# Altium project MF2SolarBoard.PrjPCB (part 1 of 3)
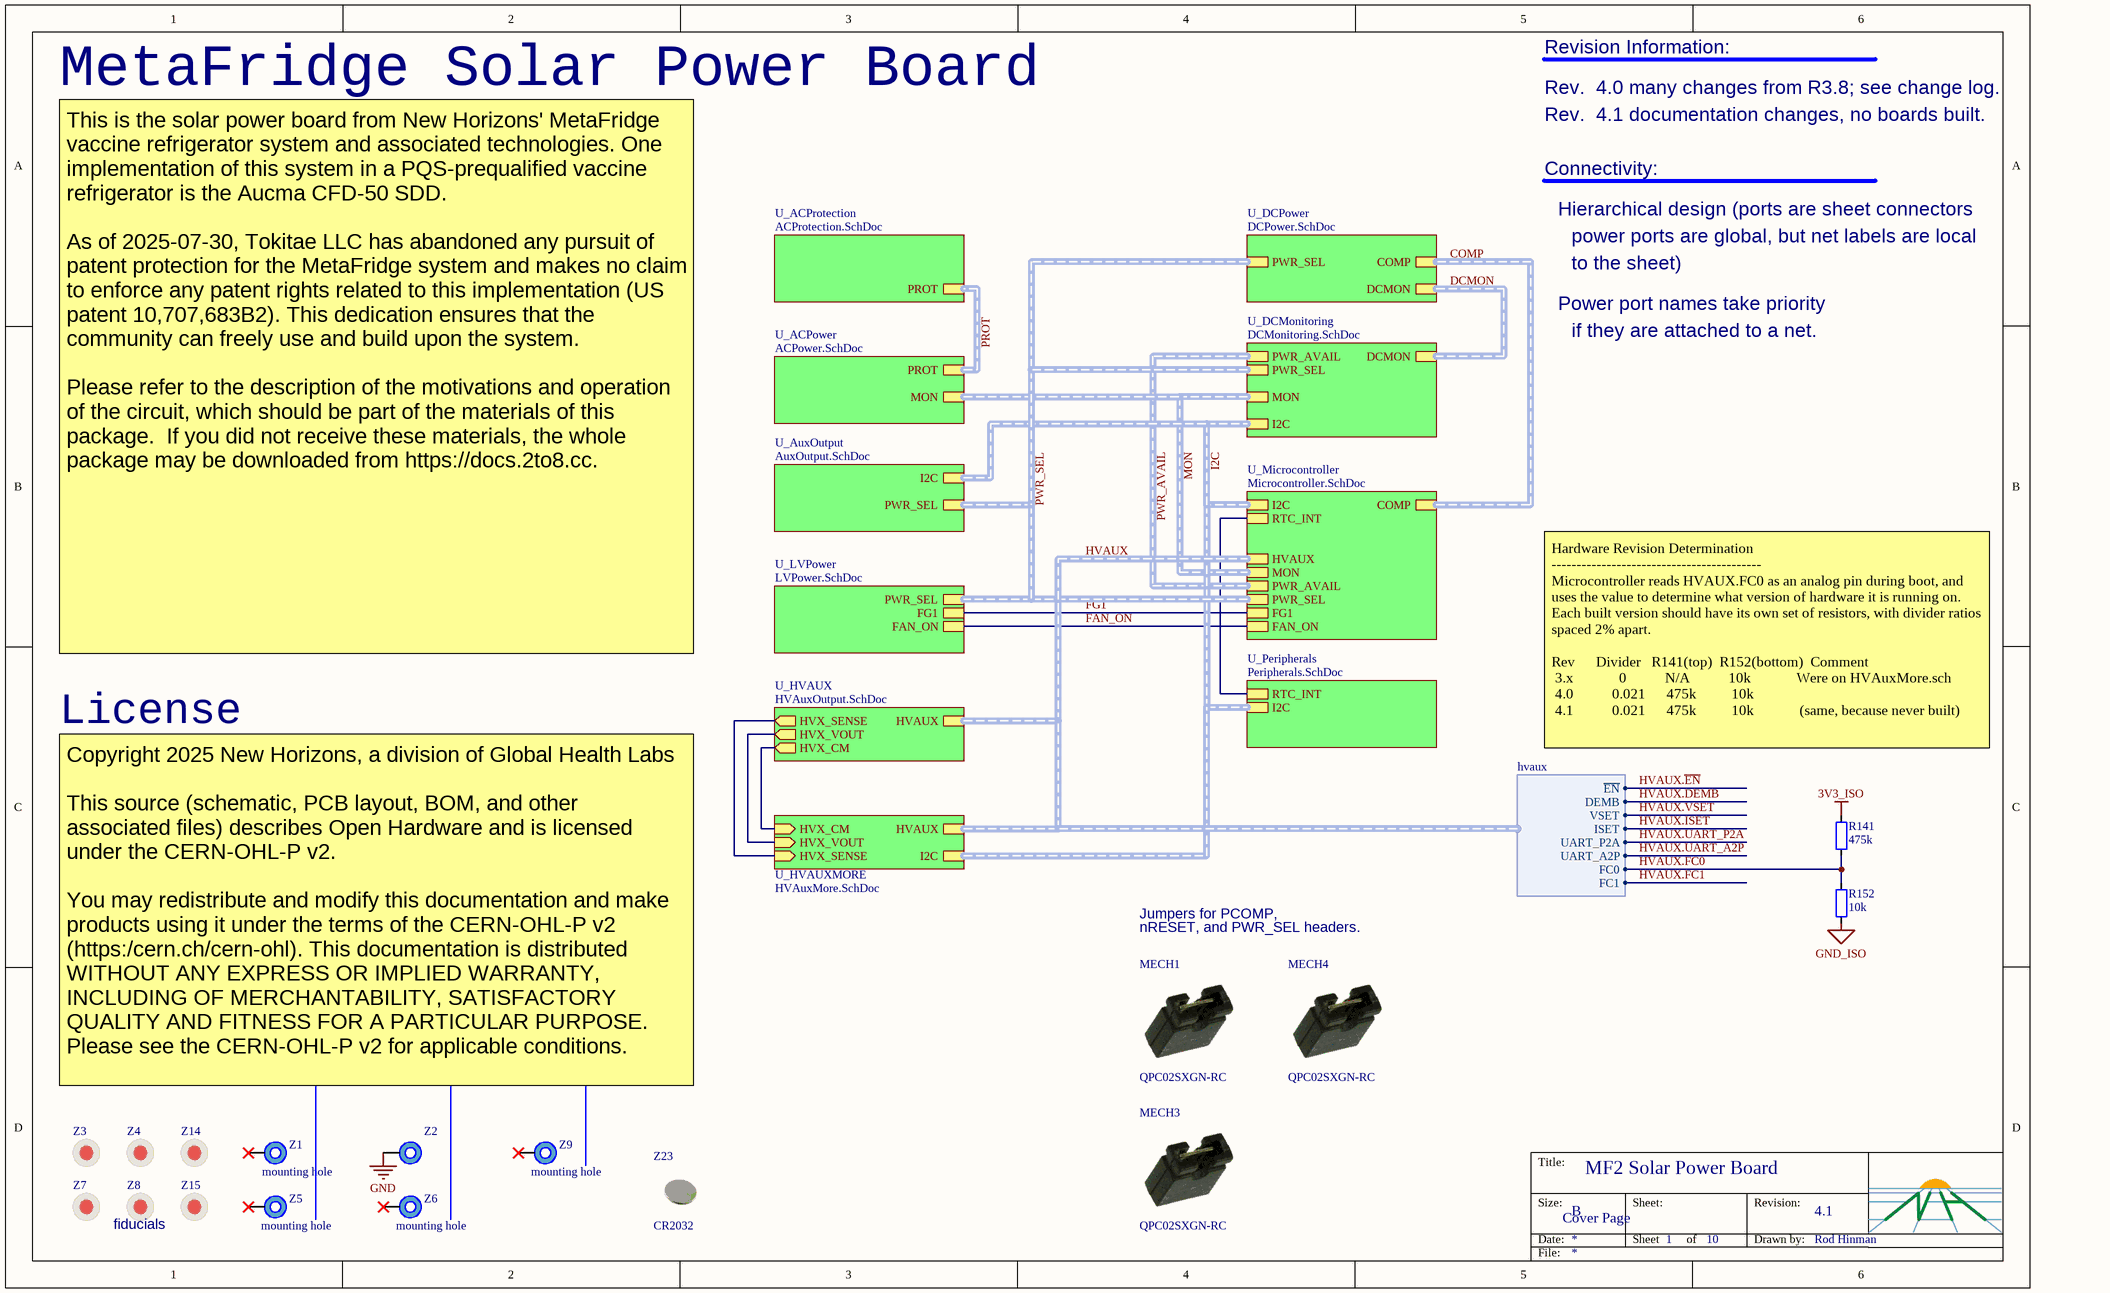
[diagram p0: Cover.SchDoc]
nhToday: 2020-03-06; nhSheetTotal: 10; nhRev: 4.1; nhProjName: MF2 Solar Power Board; nhEngPhone: 808-989-0977; nhEngName: Rod Hinman; nhEngEmail: rod@auroraresearch.com
11 sheets, 685 parts. Net scope: hierarchical (ports join the sheet entries above them; power ports are global).
Board file: PwrBrdPCB.PcbDoc
Sheets:
  Cover.SchDoc
    U_DCMonitoring = DCMonitoring.SchDoc
    U_Microcontroller = Microcontroller.SchDoc
    U_LVPower = LVPower.SchDoc
    U_DCPower = DCPower.SchDoc
    U_ACProtection = ACProtection.SchDoc
    U_ACPower = ACPower.SchDoc
    U_AuxOutput = AuxOutput.SchDoc
    U_Peripherals = Peripherals.SchDoc
    U_HVAUX = HVAuxOutput.SchDoc
    U_HVAUXMORE = HVAuxMore.SchDoc

## Sheet Cover.SchDoc
size B; SheetNumber: 1; nhSheetName: Cover Page

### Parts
MECH1  manufacturer_pn: QPC02SXGN-RC  [SULLINS_QPC02SXGN-RC]  (hidden comment: jumper)
MECH3  manufacturer_pn: QPC02SXGN-RC  [SULLINS_QPC02SXGN-RC]  (hidden comment: jumper)
MECH4  manufacturer_pn: QPC02SXGN-RC  [SULLINS_QPC02SXGN-RC]  (hidden comment: jumper)
R141  value_text: 475k  [RESC1608X05AN[0603]]  (hidden comment: 1/10W 0603 1%)
R152  value_text: 10k  [RESC1608X05AN[0603]]  (hidden comment: 1/10W 0603 1%)
Z1  mounting hole  [MOUNT_HOLE_5MM_8MM]  (no BOM)
Z2  mounting hole  [MOUNT_HOLE_5MM_8MM]  (value not drawn)  (no BOM)
Z3  NOBOM-00010  [FIDUCIAL_1_3_KEEPOUT]  (value not drawn)  (no BOM)
Z4  NOBOM-00010  [FIDUCIAL_1_3_KEEPOUT]  (value not drawn)  (no BOM)
Z5  mounting hole  [MOUNT_HOLE_5MM_8MM]  (no BOM)
Z6  mounting hole  [MOUNT_HOLE_5MM_8MM]  (no BOM)
Z7  NOBOM-00010  [FIDUCIAL_1_3_KEEPOUT]  (value not drawn)  (no BOM)
Z8  NOBOM-00010  [FIDUCIAL_1_3_KEEPOUT]  (value not drawn)  (no BOM)
Z9  mounting hole  [MOUNT_HOLE_5MM_8MM]  (no BOM)
Z14  NOBOM-00010  [FIDUCIAL_1_3_KEEPOUT]  (value not drawn)  (no BOM)
Z15  NOBOM-00010  [FIDUCIAL_1_3_KEEPOUT]  (value not drawn)  (no BOM)
Z23  CR2032  [COIN_CELL_2032]  (mechanical)

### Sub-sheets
U_ACPower = ACPower.SchDoc: PROT (harness prot), MON (harness mon-data)
U_ACProtection = ACProtection.SchDoc: PROT (harness prot)
U_AuxOutput = AuxOutput.SchDoc: I2C (harness i2c), PWR_SEL (harness pwr_sel)
U_DCMonitoring = DCMonitoring.SchDoc: MON (harness mon-data), PWR_AVAIL (harness avail), DCMON (harness dc-mon), I2C (harness i2c), PWR_SEL (harness pwr_sel)
U_DCPower = DCPower.SchDoc: COMP (harness comp), DCMON (harness dc-mon), PWR_SEL (harness pwr_sel)
U_HVAUX = HVAuxOutput.SchDoc: HVAUX (harness hvaux), HVX_CM (out), HVX_VOUT (out), HVX_SENSE (out)
U_HVAUXMORE = HVAuxMore.SchDoc: I2C (harness i2c), HVAUX (harness hvaux), HVX_CM (in), HVX_VOUT (in), HVX_SENSE (in)
U_LVPower = LVPower.SchDoc: FG1, FAN_ON, PWR_SEL (harness pwr_sel)
U_Microcontroller = Microcontroller.SchDoc: MON (harness mon-data), PWR_AVAIL (harness avail), FG1, FAN_ON, COMP (harness comp), I2C (harness i2c), RTC_INT, PWR_SEL (harness pwr_sel), HVAUX (harness hvaux)
U_Peripherals = Peripherals.SchDoc: RTC_INT, I2C (harness i2c)

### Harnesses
hvaux: ~{EN}, VSET, UART_P2A, UART_A2P, FC0, FC1, ISET, DEMB

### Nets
3V3_ISO: R141.1
GND: Z2.0
GND_ISO: R152.1
FAN_ON: sheet U_Microcontroller/FAN_ON, sheet U_LVPower/FAN_ON
FG1: sheet U_Microcontroller/FG1, sheet U_LVPower/FG1
HVAUX.FC0: R141.2 R152.2 ; sheet U_Microcontroller/HVAUX.FC0
HVX_CM: sheet U_HVAUX/HVX_CM, sheet U_HVAUXMORE/HVX_CM
HVX_VOUT: sheet U_HVAUX/HVX_VOUT, sheet U_HVAUXMORE/HVX_VOUT
RTC_INT: sheet U_Microcontroller/RTC_INT, sheet U_Peripherals/RTC_INT
NetL8_1: sheet U_HVAUX/HVX_SENSE, sheet U_HVAUXMORE/HVX_SENSE

Not connected (* = marked no-connect by the designer): Z1 0*; Z5 0*; Z6 0*; Z9 0*

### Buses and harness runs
harness COMP = sheet U_DCPower/COMP = sheet U_Microcontroller/COMP
harness DCMON = sheet U_DCMonitoring/DCMON = sheet U_DCPower/DCMON
harness HVAUX = sheet U_HVAUX/HVAUX = sheet U_HVAUXMORE/HVAUX = sheet U_Microcontroller/HVAUX
harness I2C = sheet U_AuxOutput/I2C = sheet U_DCMonitoring/I2C = sheet U_HVAUXMORE/I2C = sheet U_Microcontroller/I2C = sheet U_Peripherals/I2C
harness MON = sheet U_ACPower/MON = sheet U_DCMonitoring/MON = sheet U_Microcontroller/MON
harness PROT = sheet U_ACPower/PROT = sheet U_ACProtection/PROT
harness PWR_AVAIL = sheet U_DCMonitoring/PWR_AVAIL = sheet U_Microcontroller/PWR_AVAIL
harness PWR_SEL = sheet U_AuxOutput/PWR_SEL = sheet U_DCMonitoring/PWR_SEL = sheet U_DCPower/PWR_SEL = sheet U_LVPower/PWR_SEL = sheet U_Microcontroller/PWR_SEL

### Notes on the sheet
- MetaFridge Solar Power Board
- Rev.  4.0 many changes from R3.8; see change log.
- Revision Information:
- Rev.  4.1 documentation changes, no boards built.
- Connectivity:
- Hierarchical design (ports are sheet connectors
- power ports are global, but net labels are local
- to the sheet)
- Power port names take priority
- if they are attached to a net.
- This is the solar power board from New Horizons' MetaFridge vaccine refrigerator system and associated technologies. One implementation of this system in a PQS-prequalified vaccine refrigerator is the Aucma CFD-50 SDD.
  As of 2025-07-30, Tokitae LLC has abandoned any pursuit of patent protection for the MetaFridge system and makes no claim to enforce any patent rights related to this implementation (US patent 10,707,683B2). This dedication ensures that the community can freely use and build upon the system.
  Please refer to the description of the motivations and operation of the circuit, which should be part of the materials of this package.  If you did not receive these materials, the whole package may be downloaded from https://docs.2to8.cc.
- License
- Hardware Revision Determination
  ------------------------------------------
  Microcontroller reads HVAUX.FC0 as an analog pin during boot, and uses the value to determine what version of hardware it is running on.  Each built version should have its own set of resistors, with divider ratios spaced 2% apart.
  Rev      Divider   R141(top)  R152(bottom)  Comment
  3.x             0           N/A           10k             Were on HVAuxMore.sch
  4.0           0.021      475k          10k
  4.1           0.021      475k          10k             (same, because never built)
- Jumpers for PCOMP,
- nRESET, and PWR_SEL headers.
- Miscellaneous Mechanicals
- Copyright 2025 New Horizons, a division of Global Health Labs
  This source (schematic, PCB layout, BOM, and other associated files) describes Open Hardware and is licensed under the CERN-OHL-P v2.
  You may redistribute and modify this documentation and make products using it under the terms of the CERN-OHL-P v2 (https:/cern.ch/cern-ohl). This documentation is distributed WITHOUT ANY EXPRESS OR IMPLIED WARRANTY, INCLUDING OF MERCHANTABILITY, SATISFACTORY QUALITY AND FITNESS FOR A PARTICULAR PURPOSE. Please see the CERN-OHL-P v2 for applicable conditions.
- fiducials

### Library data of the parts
MECH1 MECH3 MECH4 = MECH-00014: 2 (1 x 2) Position Shunt Connector Black Open Top 0.100" (2.54mm) Gold; manufacturer: Sullins Connector Solutions; id: 138116
R141 = RES-00032: RES SMD 475K OHM 1% 1/10W 0603; manufacturer: Panasonic Electronic Components; manufacturer_pn: ERJ-3EKF4753V; id: 137110; value: 475000; Key Parameters: 1% required
R152 = RES-00107: 10 kOhms ±1% 0.1W, 1/10W Chip Resistor 0603 (1608 Metric) Automotive AEC-Q200 Thick Film; manufacturer_pn: ERJ-3EKF1002V; manufacturer: Panasonic Electronic Components; id: 182861; value: 10000; Key Parameters: 1% required
Z1 Z2 Z5 Z6 Z9 = NOBOM-00011: Mounting hole, 5mm hole, 8mm pad; manufacturer: New Horizons; id: 138119
Z3 Z4 Z7 Z8 Z14 Z15 = NOBOM-00010: Fiducial, 1mm dia, 3mm solder mask opening; manufacturer: New Horizons; id: 138118
Z23 = MECH-00025: Lithium Battery Non-Rechargeable (Primary) 3V Coin, 20.0mm; manufacturer: Panasonic Electronic Components; id: 141799

## Sheet DCMonitoring.SchDoc
size B; SheetNumber: 3; nhSheetName: DC Monitoring
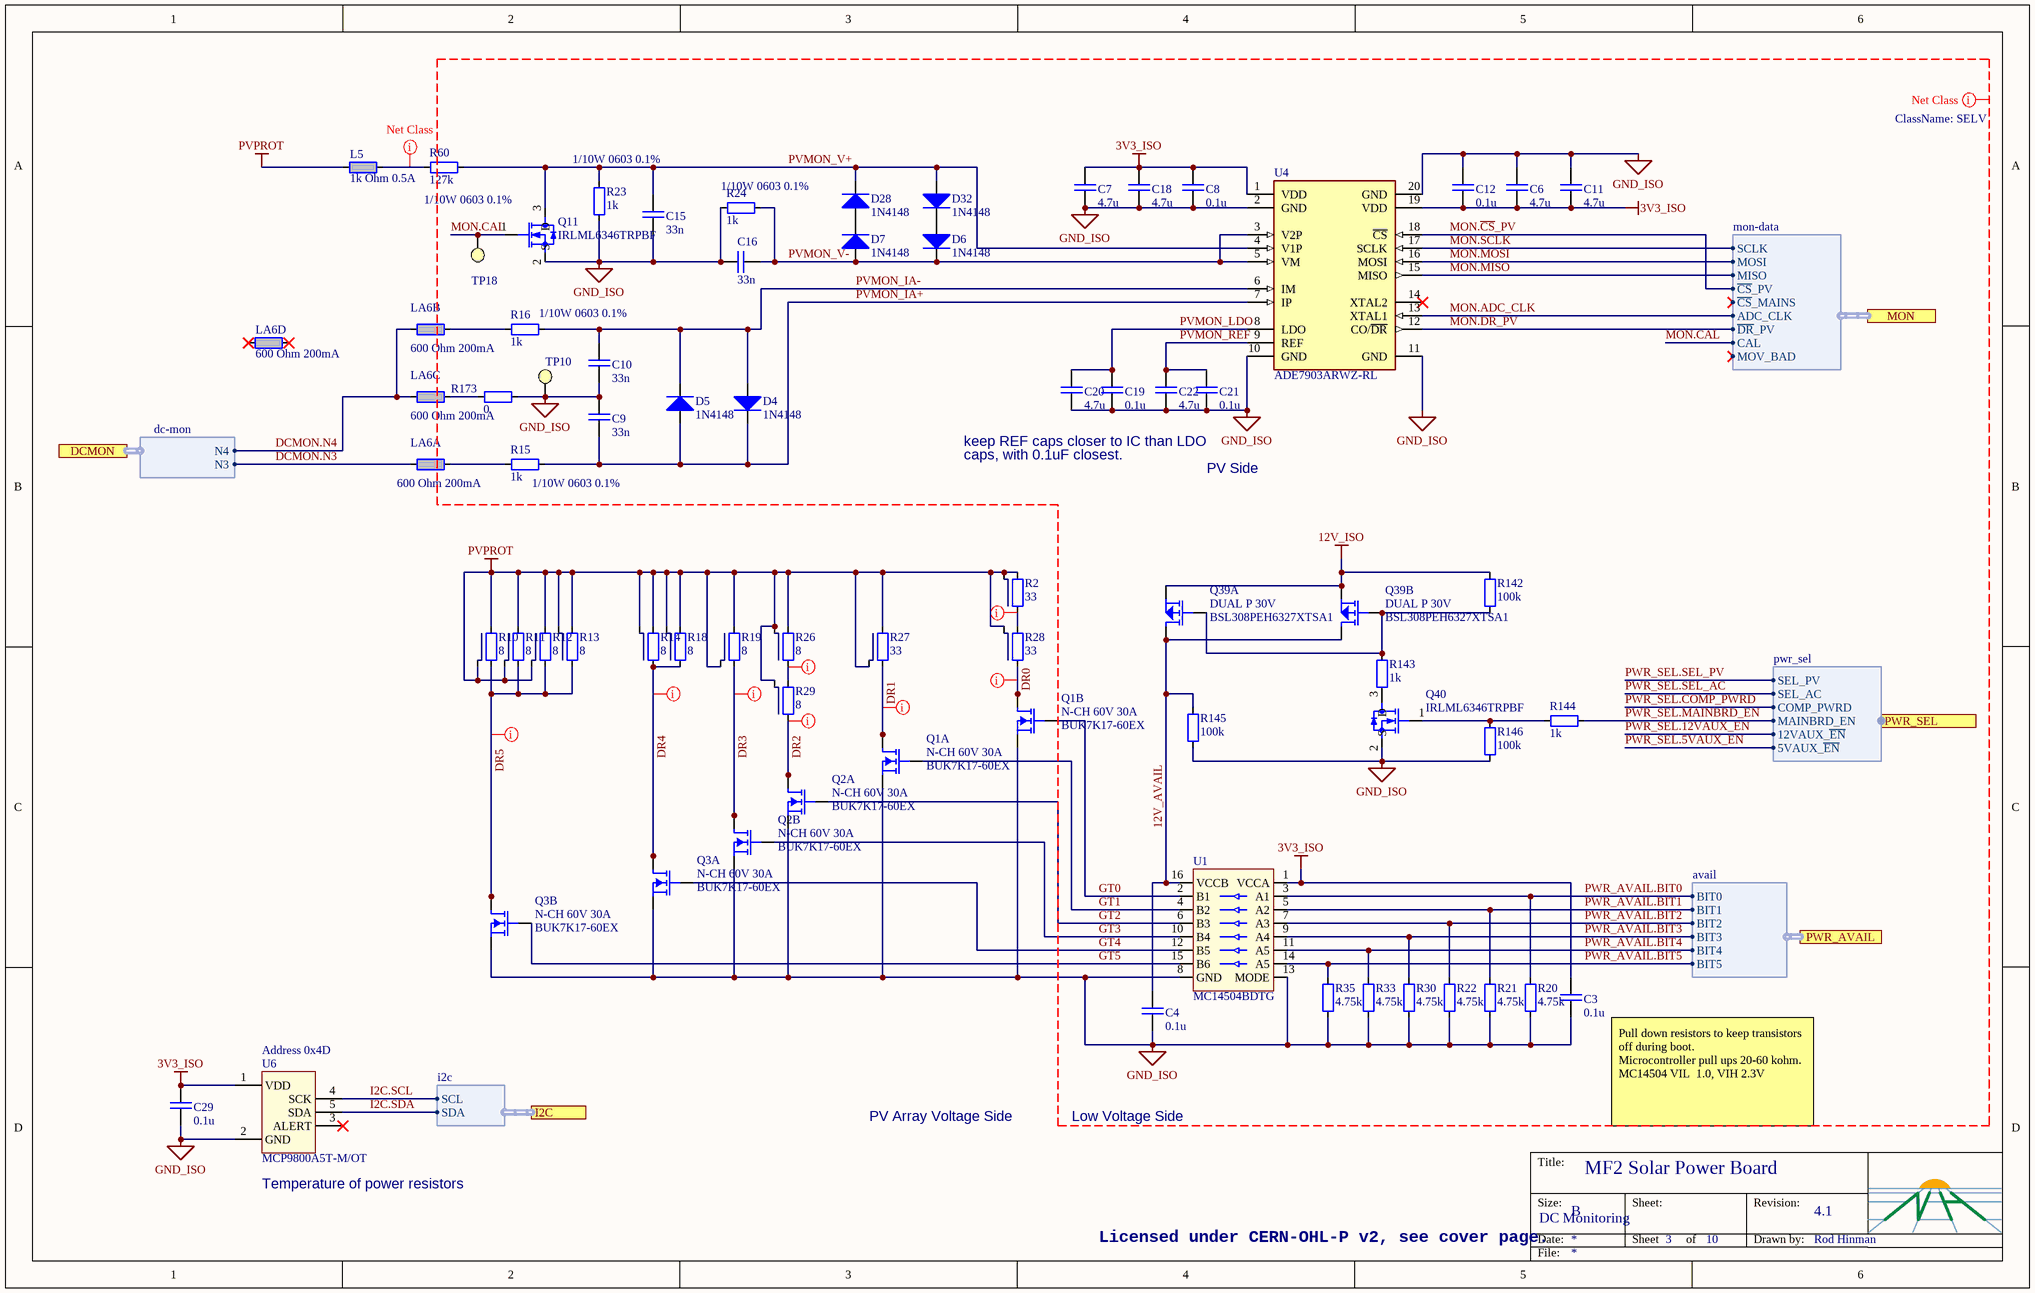
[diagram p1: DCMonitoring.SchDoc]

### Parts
C3  value_text: 0.1u  [CAPC1608X09N[0603]]  (hidden comment: 50V X7R 0603)
C4  value_text: 0.1u  [CAPC1608X09N[0603]]  (hidden comment: 50V X7R 0603)
C6  value_text: 4.7u  [CAPC1608X09N[0603]]  (hidden comment: 25V X6S 0603)
C7  value_text: 4.7u  [CAPC1608X09N[0603]]  (hidden comment: 25V X6S 0603)
C8  value_text: 0.1u  [CAPC1608X09N[0603]]  (hidden comment: 50V X7R 0603)
C9  value_text: 33n  [CAPC1608X09N[0603]]  (hidden comment: 50V X7R 0603)
C10  value_text: 33n  [CAPC1608X09N[0603]]  (hidden comment: 50V X7R 0603)
C11  value_text: 4.7u  [CAPC1608X09N[0603]]  (hidden comment: 25V X6S 0603)
C12  value_text: 0.1u  [CAPC1608X09N[0603]]  (hidden comment: 50V X7R 0603)
C15  value_text: 33n  [CAPC1608X09N[0603]]  (hidden comment: 50V X7R 0603)
C16  value_text: 33n  [CAPC1608X09N[0603]]  (hidden comment: 50V X7R 0603)
C18  value_text: 4.7u  [CAPC1608X09N[0603]]  (hidden comment: 25V X6S 0603)
C19  value_text: 0.1u  [CAPC1608X09N[0603]]  (hidden comment: 50V X7R 0603)
C20  value_text: 4.7u  [CAPC1608X09N[0603]]  (hidden comment: 25V X6S 0603)
C21  value_text: 0.1u  [CAPC1608X09N[0603]]  (hidden comment: 50V X7R 0603)
C22  value_text: 4.7u  [CAPC1608X09N[0603]]  (hidden comment: 25V X6S 0603)
C29  value_text: 0.1u  [CAPC1608X09N[0603]]  (hidden comment: 50V X7R 0603)
D4  1N4148  [SOD-123]
D5  1N4148  [SOD-123]
D6  1N4148  [SOD-123]
D7  1N4148  [SOD-123]
D28  1N4148  [SOD-123]
D32  1N4148  [SOD-123]
L5  1k Ohm 0.5A  [INDC2012X110N[0805]]
LA6  600 Ohm 200mA  [FERCAV80P320X160X70-4]  (parts A,B,C,D of 4)
Q1  N-CH 60V 30A  manufacturer_pn: BUK7K17-60EX  [SOT1205_LFPAK56D]  (parts A,B of 2)
Q2  N-CH 60V 30A  manufacturer_pn: BUK7K17-60EX  [SOT1205_LFPAK56D]  (parts A,B of 2)
Q3  N-CH 60V 30A  manufacturer_pn: BUK7K17-60EX  [SOT1205_LFPAK56D]  (parts A,B of 2)
Q11  manufacturer_pn: IRLML6346TRPBF  [SOT23-3]  (hidden comment: N-CH 30V 3.4A)
Q39  DUAL P 30V  manufacturer_pn: BSL308PEH6327XTSA1  [SOT_23_6]  (parts A,B of 2)
Q40  manufacturer_pn: IRLML6346TRPBF  [SOT23-3]  (hidden comment: N-CH 30V 3.4A)
R2  value_text: 33  [BOURNS_PWR163]  (hidden comment: 25W DPAK 1%)
R10  value_text: 8  [TO263_PWR_RES]  (hidden comment: 35W D2PAK 1%)
R11  value_text: 8  [TO263_PWR_RES]  (hidden comment: 35W D2PAK 1%)
R12  value_text: 8  [TO263_PWR_RES]  (hidden comment: 35W D2PAK 1%)
R13  value_text: 8  [TO263_PWR_RES]  (hidden comment: 35W D2PAK 1%)
R14  value_text: 8  [TO263_PWR_RES]  (hidden comment: 35W D2PAK 1%)
R15  1/10W 0603 0.1%  value_text: 1k  [RESC1608X05AN[0603]]
R16  1/10W 0603 0.1%  value_text: 1k  [RESC1608X05AN[0603]]
R18  value_text: 8  [TO263_PWR_RES]  (hidden comment: 35W D2PAK 1%)
R19  value_text: 8  [TO263_PWR_RES]  (hidden comment: 35W D2PAK 1%)
R20  value_text: 4.75k  [RESC1608X05AN[0603]]  (hidden comment: 1/10W 0603 1%)
R21  value_text: 4.75k  [RESC1608X05AN[0603]]  (hidden comment: 1/10W 0603 1%)
R22  value_text: 4.75k  [RESC1608X05AN[0603]]  (hidden comment: 1/10W 0603 1%)
R23  1/10W 0603 0.1%  value_text: 1k  [RESC1608X05AN[0603]]
R24  1/10W 0603 0.1%  value_text: 1k  [RESC1608X05AN[0603]]
R26  value_text: 8  [TO263_PWR_RES]  (hidden comment: 35W D2PAK 1%)
R27  value_text: 33  [BOURNS_PWR163]  (hidden comment: 25W DPAK 1%)
R28  value_text: 33  [BOURNS_PWR163]  (hidden comment: 25W DPAK 1%)
R29  value_text: 8  [TO263_PWR_RES]  (hidden comment: 35W D2PAK 1%)
R30  value_text: 4.75k  [RESC1608X05AN[0603]]  (hidden comment: 1/10W 0603 1%)
R33  value_text: 4.75k  [RESC1608X05AN[0603]]  (hidden comment: 1/10W 0603 1%)
R35  value_text: 4.75k  [RESC1608X05AN[0603]]  (hidden comment: 1/10W 0603 1%)
R60  1/10W 0603 0.1%  value_text: 127k  [RESC1608X05AN[0603]]
R142  value_text: 100k  [RESC1608X05AN[0603]]  (hidden comment: 1/10W 0603 1%)
R143  value_text: 1k  [RESC1608X05AN[0603]]  (hidden comment: 1/10W 0603 1%)
R144  value_text: 1k  [RESC1608X05AN[0603]]  (hidden comment: 1/10W 0603 1%)
R145  value_text: 100k  [RESC1608X05AN[0603]]  (hidden comment: 1/10W 0603 1%)
R146  value_text: 100k  [RESC1608X05AN[0603]]  (hidden comment: 1/10W 0603 1%)
R173  value_text: 0  [RESC1608X05AN[0603]]  (hidden comment: 1/10W 0603 Jumper)
TP10  TP SMD 1.5mm  [TP_SMD_Ø1.5mm]  (value not drawn)  (no BOM)
TP18  TP SMD 1.5mm  [TP_SMD_Ø1.5mm]  (value not drawn)  (no BOM)
U1  manufacturer_pn: MC14504BDTG  [TSSOP16_ON]  (hidden comment: Logic level translator)
U4  manufacturer_pn: ADE7903ARWZ-RL  [SOIC127P1030X265-20N_smaller]  (hidden comment: ADE7903)
U6  Address 0x4D  manufacturer_pn: MCP9800A5T-M/OT  [SOT-23-5]

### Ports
DCMON (harness dc-mon), I2C (harness i2c), MON (harness mon-data), PWR_AVAIL (harness avail), PWR_SEL (harness pwr_sel)

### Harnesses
dc-mon: N4, N3
avail: BIT0, BIT1, BIT2, BIT3, BIT5, BIT4
mon-data: SCLK, MOSI, MISO, ~{CS}_PV, ADC_CLK, ~{DR}_PV, ~{CS}_MAINS, MOV_BAD, CAL
i2c: SDA, SCL
pwr_sel: SEL_PV, SEL_AC, COMP_PWRD, 12VAUX_~{EN}, 5VAUX_~{EN}, MAINBRD_EN

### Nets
3V3_ISO: C3.1 C6.2 C7.1 C8.1 C11.2 C12.2 C18.1 C29.1 U1.1(VCCA) U4.1(VDD) U4.19(VDD) U6.1(VDD)
12V_ISO: Q39.2(S2) Q39.5(S1) R142.2
GND_ISO: C3.2 C4.2 C6.1 C7.2 C8.2 C9.2 C10.1 C11.1 C12.1 C15.2 C16.2 C18.2 C19.2 C20.2 C21.2 C22.2 C29.2 Q1.1(S1) Q1.3(S2) Q2.1(S1) Q2.3(S2) Q3.1(S1) Q3.3(S2) Q11.2(S) Q40.2(S) R20.2 R21.2 R22.1 R23.1 R24.1 R30.2 R33.2 R35.1 R145.1 R146.1 R173.2 TP10.1 U1.8(GND) U1.13(MODE) U4.2(GND) U4.10(GND) U4.11(GND) U4.20(GND) U6.2(GND)
PVPROT: L5.1 R2.2 R2.3 R10.1 R10.3 R11.1 R11.3 R12.1 R12.3 R13.2 R13.3 R14.2 R14.3 R18.2 R18.3 R19.1 R19.3 R26.2 R26.3 R27.1 R27.3 R28.3 R29.3
12V_AVAIL: C4.1 Q39.4(D2) Q39.6(D1) R145.2 U1.16(VCCB)
DCMON.N3: LA6.1 ; port DCMON.N3
DCMON.N4: LA6.2 LA6.3 ; port DCMON.N4
DR0: Q1.5(D2) Q1.6(D2) R28.1
DR1: Q1.7(D1) Q1.8(D1) R27.2
DR2: Q2.7(D1) Q2.8(D1) R29.1
DR3: Q2.5(D2) Q2.6(D2) R19.2
DR4: Q3.7(D1) Q3.8(D1) R14.1 R18.1
DR5: Q3.5(D2) Q3.6(D2) R10.2 R11.2 R12.2 R13.1
GT0: Q1.4(G2) U1.2(B1)
GT1: Q1.2(G1) U1.4(B2)
GT2: Q2.2(G1) U1.6(B3)
GT3: Q2.4(G2) U1.10(B4)
GT4: Q3.2(G1) U1.12(B5)
GT5: Q3.4(G2) U1.15(B6)
I2C.SCL: U6.4(SCK) ; port I2C.SCL
I2C.SDA: U6.5(SDA) ; port I2C.SDA
MON.ADC_CLK: U4.13(XTAL1) ; port MON.ADC_CLK
MON.~{CS}_PV: U4.18(~{CS}) ; port MON.~{CS}_PV
MON.CAL: Q11.1(G) TP18.1 ; port MON.CAL
MON.~{DR}_PV: U4.12(CO/~{DR}) ; port MON.~{DR}_PV
MON.MISO: U4.15(MISO) ; port MON.MISO
MON.MOSI: U4.16(MOSI) ; port MON.MOSI
MON.SCLK: U4.17(SCLK) ; port MON.SCLK
PVMON_IA+: C9.1 D4.K D5.A R15.2 U4.7(IP)
PVMON_IA-: C10.2 D4.A D5.K R16.1 U4.6(IM)
PVMON_LDO: C19.1 C20.1 U4.8(LDO)
PVMON_REF: C21.1 C22.1 U4.9(REF)
PVMON_V+: C15.1 D28.K D32.A Q11.3(D) R23.2 R60.2 U4.4(V1P)
PVMON_V-: C16.1 D6.K D7.A R24.2 U4.3(V2P) U4.5(VM)
PWR_AVAIL.BIT0: R20.1 U1.3(A1) ; port PWR_AVAIL.BIT0
PWR_AVAIL.BIT1: R21.1 U1.5(A2) ; port PWR_AVAIL.BIT1
PWR_AVAIL.BIT2: R22.2 U1.7(A3) ; port PWR_AVAIL.BIT2
PWR_AVAIL.BIT3: R30.1 U1.9(A4) ; port PWR_AVAIL.BIT3
PWR_AVAIL.BIT4: R33.1 U1.11(A5) ; port PWR_AVAIL.BIT4
PWR_AVAIL.BIT5: R35.2 U1.14(A5) ; port PWR_AVAIL.BIT5
PWR_SEL.MAINBRD_EN: R144.1 ; port PWR_SEL.MAINBRD_EN
NetD6_A: D6.A D32.K
NetD7_K: D7.K D28.A
NetL5_2: L5.2 R60.1
NetLA6_6: LA6.6 R173.1
NetLA6_7: LA6.7 R16.2
NetLA6_8: LA6.8 R15.1
NetQ39_1: Q39.1(G1) Q39.3(G2) R142.1 R143.2
NetQ40_1: Q40.1(G) R144.2 R146.2
NetQ40_3: Q40.3(D) R143.1
NetR2_1: R2.1 R28.2
NetR26_1: R26.1 R29.2

Not connected (* = marked no-connect by the designer): LA6 4* 5*; U4 14(XTAL2)*; U6 3(ALERT)*

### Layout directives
net class PVPOS: DR0, DR1, DR2, DR3, DR4, DR5, NetL5_2, NetR2_1, NetR26_1
net class SELV: 3V3_ISO, 12V_AVAIL, 12V_ISO, DR0, DR1, DR2, DR3, DR4, DR5, GND_ISO, GT0, GT1, GT2, GT3, GT4, GT5, MON.ADC_CLK, MON.CAL, MON.MISO, MON.MOSI, MON.SCLK, MON.~{CS}_PV, MON.~{DR}_PV, PVMON_IA+, PVMON_IA-, PVMON_LDO, PVMON_REF, PVMON_V+, PVMON_V-, PVPROT, PWR_AVAIL.BIT0, PWR_AVAIL.BIT1, PWR_AVAIL.BIT2, PWR_AVAIL.BIT3, PWR_AVAIL.BIT4, PWR_AVAIL.BIT5, PWR_SEL.5VAUX_~{EN}, PWR_SEL.12VAUX_~{EN}, PWR_SEL.COMP_PWRD, PWR_SEL.MAINBRD_EN, PWR_SEL.SEL_AC, PWR_SEL.SEL_PV

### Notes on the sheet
- keep REF caps closer to IC than LDO
- caps, with 0.1uF closest.
- PV Side
- PV Array Voltage Side
- Low Voltage Side
- (near C3) Pull down resistors to keep transistors off during boot.
  Microcontroller pull ups 20-60 kohm.
  MC14504 VIL  1.0, VIH 2.3V
- (near U6) Temperature of power resistors
- Licensed under CERN-OHL-P v2, see cover page.

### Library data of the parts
C3 C4 C8 C12 C19 C21 C29 = CAP-00001: 0.10µF 50V Ceramic Capacitor X7R 0603 (1608 Metric) 0.063" L x 0.031" W (1.60mm x 0.80mm); manufacturer: Murata Electronics North America; manufacturer_pn: GRM188R71H104KA93D; id: 136482; value: 1E-7; Key Parameters: V >= 25V
C6 C7 C11 C18 C20 C22 = CAP-00015: 4.7µF 25V Ceramic Capacitor X6S 0603 (1608 Metric) 0.063" L x 0.031" W (1.60mm x 0.80mm); manufacturer: Murata Electronics North America; manufacturer_pn: GRM188C81E475KE11D; id: 136726; value: 4.7E-6; Key Parameters: V >= 16V
C9 C10 C15 C16 = CAP-00000: 0.033µF 50V Ceramic Capacitor X7R 0603 (1608 Metric) 0.063" L x 0.031" W (1.60mm x 0.80mm); manufacturer: Murata Electronics North America; manufacturer_pn: GRM188R71H333KA61D; id: 136460; value: 3.3E-8; Key Parameters: V >= 16V
D4-D7 D28 D32 = DIO-00004: Diode Standard 100V 150mA Surface Mount SOD-123; manufacturer_pn: 1N4148W-TP; manufacturer: Micro Commercial Co; id: 137134
L5 = FER-00005: FERRITE BEAD 1 KOHM 0805 1LN 0.28 ohm; manufacturer: Murata Electronics North America; manufacturer_pn: BLM21AG102SN1D; id: 137114; value: 1000
LA6 = FER-00009: FERRITE BEAD 600 OHM 1206 4LN; manufacturer_pn: BK32164S601-T; manufacturer: Taiyo Yuden; id: 162218; value: 600
Q1-Q3 = FET-00017: Mosfet Array 2 N-Channel (Dual) 60V 30A 53W Surface Mount LFPAK56D; manufacturer: Nexperia USA Inc.; id: 193253
Q11 Q40 = FET-00002: MOSFET N-CH 30V 3.4A SOT23; manufacturer: Infineon Technologies; id: 137229
Q39 = FET-00023: Mosfet Array 2 P-Channel (Dual) 30V 2A 500mW Surface Mount PG-TSOP-6-6; manufacturer: Infineon Technologies; id: 297421
R2 R27 R28 = RES-00083: RES SMD 33 OHM 1% 25W DPAK; manufacturer_pn: PWR163S-25-33R0F; manufacturer: Bourns Inc.; id: 152903; value: 33
R10-R14 R18 R19 R26 R29 = RES-00082: RES SMD 8 OHM 1% 35W D2PAK; manufacturer_pn: PWR263S-35-8R00F; manufacturer: Bourns Inc.; id: 152902; value: 8
R15 R16 R23 R24 = RES-00067: RES SMD 1KOHM 0.1% 1/10W 0603; manufacturer: Panasonic Electronic Components; manufacturer_pn: ERA-3AEB102V; id: 147997; value: 1000; Key Parameters: 0.1% required
R20-R22 R30 R33 = RES-00013: RES SMD 4.75K OHM 1% 1/10W 0603; manufacturer_pn: ERJ-3EKF4751V; manufacturer: Panasonic Electronic Components; id: 137091; value: 4750; Key Parameters: 5% OK
R35 = RES-00013: RES SMD 4.75K OHM 1% 1/10W 0603; manufacturer: Panasonic Electronic Components; manufacturer_pn: ERJ-3EKF4751V; id: 137091; value: 4750; Key Parameters: 5% OK
R60 = RES-00066: RES SMD 127KOHM 0.1% 1/10W 0603; manufacturer: Panasonic Electronic Components; manufacturer_pn: ERA-3AEB1273V; id: 147994; value: 127000; Key Parameters: 0.1% required
R142 R145 R146 = RES-00112: 100 kOhms ±1% 0.1W, 1/10W Chip Resistor 0603 (1608 Metric) Automotive AEC-Q200 Thick Film; manufacturer: Panasonic Electronic Components; manufacturer_pn: ERJ-3EKF1003V; id: 185358; value: 100000; Key Parameters: 1% required
R143 R144 = RES-00113: 1 kOhms ±1% 0.1W, 1/10W Chip Resistor 0603 (1608 Metric) Automotive AEC-Q200 Thick Film; manufacturer: Panasonic Electronic Components; manufacturer_pn: ERJ-3EKF1001V; id: 185365; value: 1000; Key Parameters: 1% required
R173 = RES-00010: RES SMD 0.0OHM JUMPER 1/10W 0603; manufacturer_pn: ERJ-3GEY0R00V; manufacturer: Panasonic Electronic Components; id: 137088; value: 0
TP10 TP18 = NOBOM-00008: Test point, SMD, 1.5mm dia (0.059"); manufacturer: New Horizons; id: 137590
U1 = ICXCV-00015: IC LEVEL SHIFTER HEX 16-TSSOP; manufacturer: ON Semiconductor; id: 171400
U4 = ICANA-00022: Energy Monitor (Power Meter) 24 bit SPI 20-SOIC; manufacturer: Analog Devices Inc.; id: 169235
U6 = ICANA-00026: Temperature Sensor Digital, Local -55°C ~ 125°C 11 b SOT-23-5; manufacturer: Microchip Technology; id: 178864

## Sheet Microcontroller.SchDoc
size B; SheetNumber: 10; nhSheetName: Microcontroller
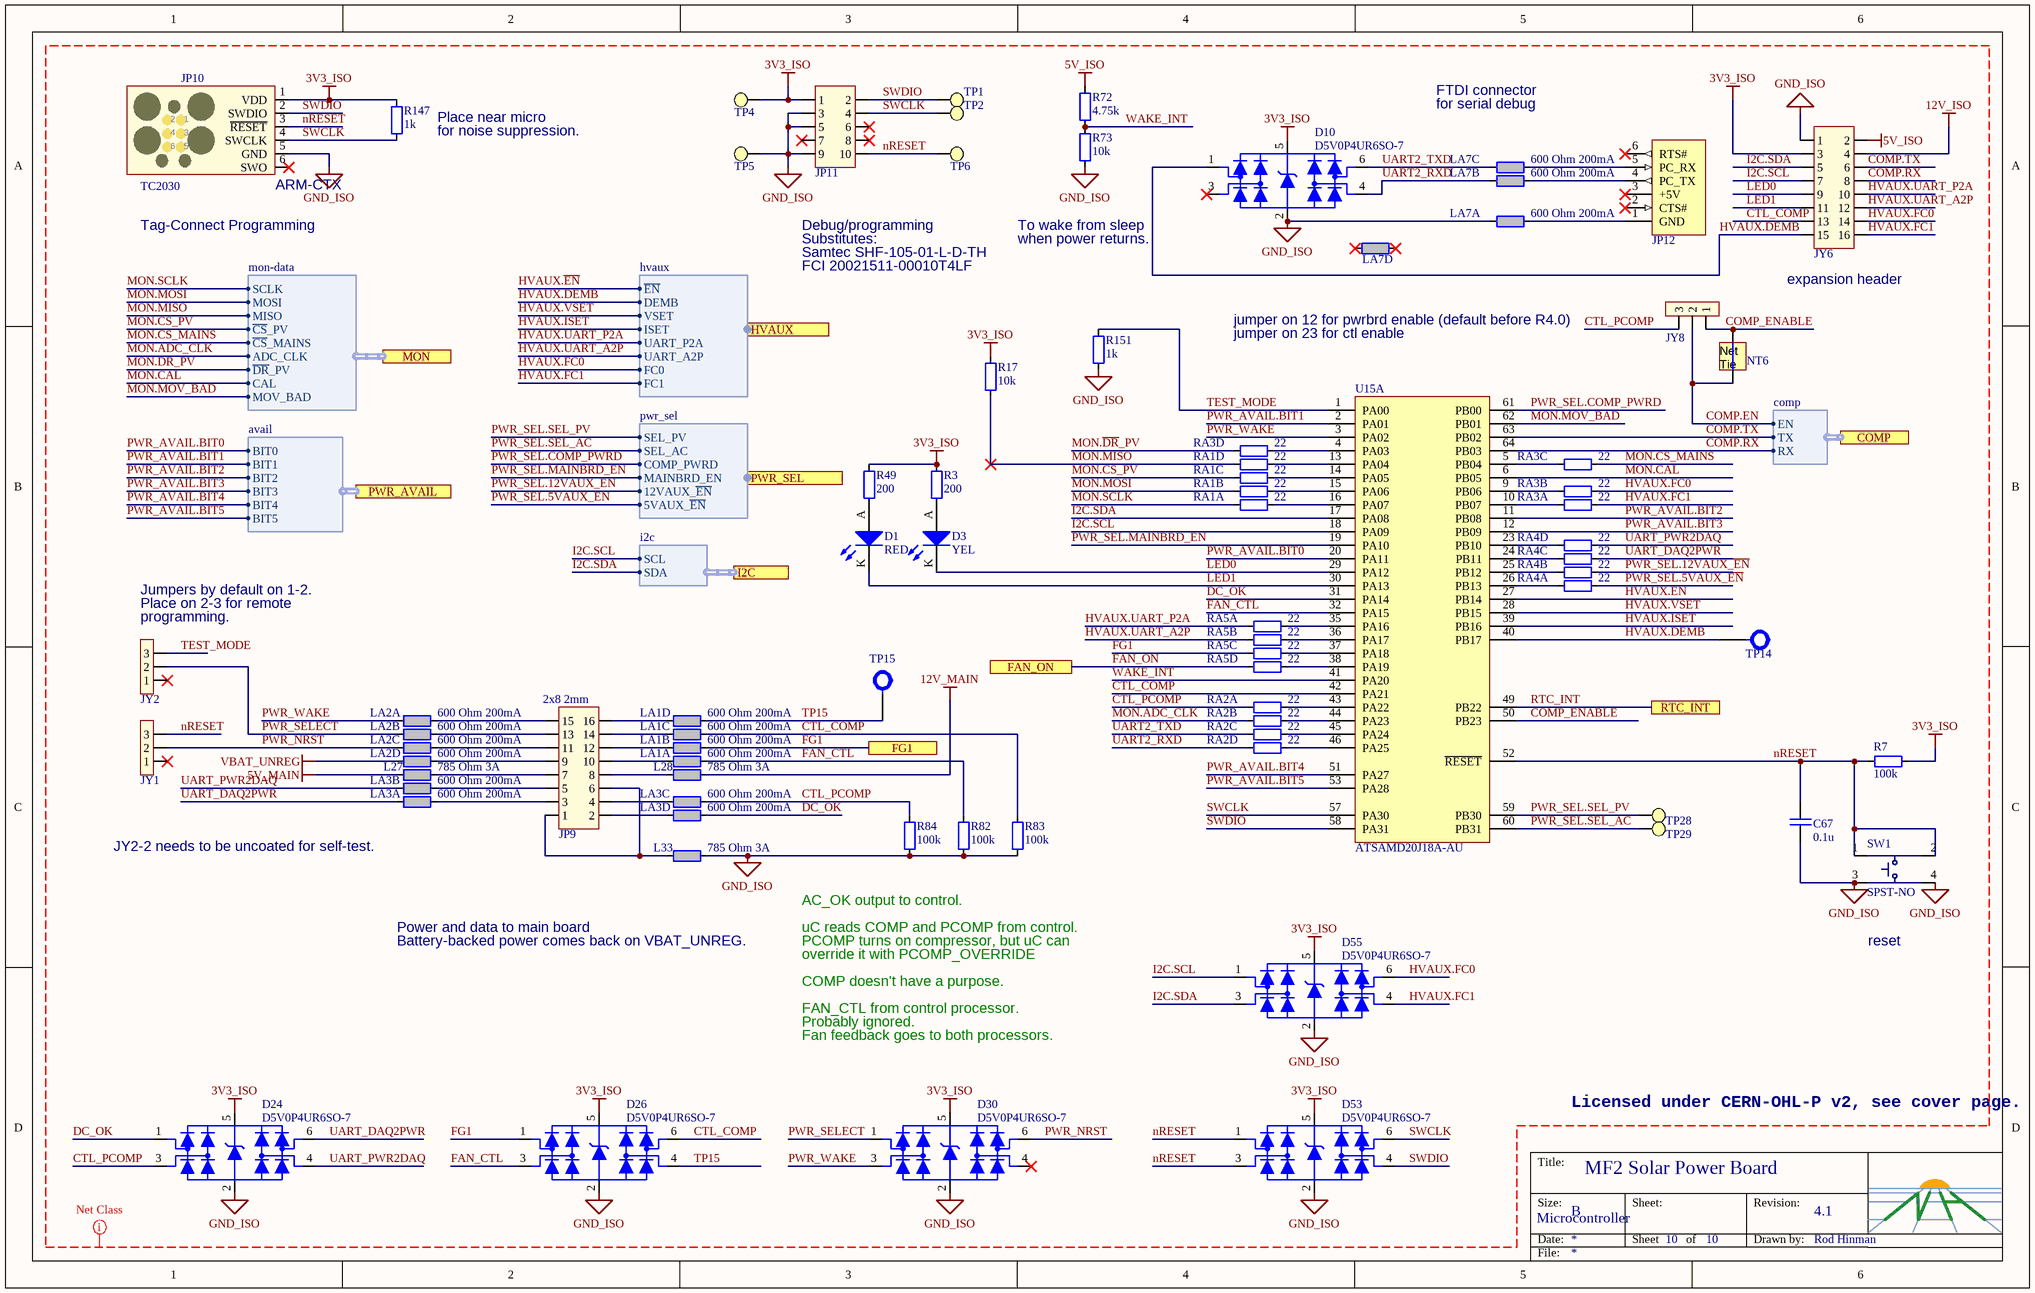
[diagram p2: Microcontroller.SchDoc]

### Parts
C67  value_text: 0.1u  [CAPC1608X09N[0603]]  (hidden comment: 50V X7R 0603)
D1  RED  [LEDC1608X06NRED,0603,]
D3  YEL  [LEDC1608X06NYEL,0603,]
D10  manufacturer_pn: D5V0P4UR6SO-7  [SOT23-6]  (hidden comment: TVS)
D24  manufacturer_pn: D5V0P4UR6SO-7  [SOT23-6]  (hidden comment: TVS)
D26  manufacturer_pn: D5V0P4UR6SO-7  [SOT23-6]  (hidden comment: TVS)
D30  manufacturer_pn: D5V0P4UR6SO-7  [SOT23-6]  (hidden comment: TVS)
D53  manufacturer_pn: D5V0P4UR6SO-7  [SOT23-6]  (hidden comment: TVS)
D55  manufacturer_pn: D5V0P4UR6SO-7  [SOT23-6]  (hidden comment: TVS)
JP9  2x8 2mm  [MOLEX_0559171610]
JP10  TC2030  [TAG-TC2030-LEGS]  (no BOM)
JP11  2x5 1.27mm  [CNC_3220-10-0100-00]  (value not drawn)
JP12  1x6 0.1in  [HDR_6PIN]  (value not drawn)
JY1  1x3 0.1in  [HDR_3PIN]  (value not drawn)
JY2  1x3 0.1in  [HDR_3PIN]  (value not drawn)
JY6  2x8 0.1"  [SULLINS_PRPC008DAAN-RC]  (value not drawn)
JY8  1x3 0.1in  [HDR_3PIN]  (value not drawn)
L27  785 Ohm 3A  [INDC4532X17N[1812]]
L28  785 Ohm 3A  [INDC4532X17N[1812]]
L33  785 Ohm 3A  [INDC4532X17N[1812]]
LA1  600 Ohm 200mA  [FERCAV80P320X160X70-4]  (parts A,B,C,D of 4)
LA2  600 Ohm 200mA  [FERCAV80P320X160X70-4]  (parts A,B,C,D of 4)
LA3  600 Ohm 200mA  [FERCAV80P320X160X70-4]  (parts A,B,C,D of 4)
LA7  600 Ohm 200mA  [FERCAV80P320X160X70-4]  (parts A,B,C,D of 4)
NT6  Net Tie  [NETTIE_0.254mm_NOPADS]  (value not drawn)  (net tie, no BOM)
R3  value_text: 200  [RESC1608X05AN[0603]]  (hidden comment: 1/10W 0603 1%)
R7  value_text: 100k  [RESC1608X05AN[0603]]  (hidden comment: 1/10W 0603 1%)
R17  value_text: 10k  [RESC1608X05AN[0603]]  (hidden comment: 1/10W 0603 1%)
R49  value_text: 200  [RESC1608X05AN[0603]]  (hidden comment: 1/10W 0603 1%)
R72  value_text: 4.75k  [RESC1608X05AN[0603]]  (hidden comment: 1/10W 0603 1%)
R73  value_text: 10k  [RESC1608X05AN[0603]]  (hidden comment: 1/10W 0603 1%)
R82  value_text: 100k  [RESC1608X05AN[0603]]  (hidden comment: 1/10W 0603 1%)
R83  value_text: 100k  [RESC1608X05AN[0603]]  (hidden comment: 1/10W 0603 1%)
R84  value_text: 100k  [RESC1608X05AN[0603]]  (hidden comment: 1/10W 0603 1%)
R147  value_text: 1k  [RESC1608X05AN[0603]]  (hidden comment: 1/10W 0603 1%)
R151  value_text: 1k  [RESC1608X05AN[0603]]  (hidden comment: 1/10W 0603 1%)
RA1  value 22  [RESCAV80P320X160X70-8]  (hidden comment: 22 5%)  (parts A,B,C,D of 4)
RA2  value 22  [RESCAV80P320X160X70-8]  (hidden comment: 22 5%)  (parts A,B,C,D of 4)
RA3  value 22  [RESCAV80P320X160X70-8]  (hidden comment: 22 5%)  (parts A,B,C,D of 4)
RA4  value 22  [RESCAV80P320X160X70-8]  (hidden comment: 22 5%)  (parts A,B,C,D of 4)
RA5  value 22  [RESCAV80P320X160X70-8]  (hidden comment: 22 5%)  (parts A,B,C,D of 4)
SW1  SPST-NO  [TE_FSM2JH]
TP1  TP SMD 1.5mm  [TP_SMD_Ø1.5mm]  (value not drawn)  (no BOM)
TP2  TP SMD 1.5mm  [TP_SMD_Ø1.5mm]  (value not drawn)  (no BOM)
TP4  TP SMD 1.5mm  [TP_SMD_Ø1.5mm]  (value not drawn)  (no BOM)
TP5  TP SMD 1.5mm  [TP_SMD_Ø1.5mm]  (value not drawn)  (no BOM)
TP6  TP SMD 1.5mm  [TP_SMD_Ø1.5mm]  (value not drawn)  (no BOM)
TP14  TP TH  0.78mm  [TP_TH078H127P]  (value not drawn)  (no BOM)
TP15  TP TH  0.78mm  [TP_TH078H127P]  (value not drawn)  (no BOM)
TP28  TP SMD 1.5mm  [TP_SMD_Ø1.5mm]  (value not drawn)  (no BOM)
TP29  TP SMD 1.5mm  [TP_SMD_Ø1.5mm]  (value not drawn)  (no BOM)
U15  manufacturer_pn: ATSAMD20J18A-AU  [ATM-TQFP64]  (hidden comment: 48MHz 256k 32k)  (part A of 2)

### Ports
COMP (harness comp), FAN_ON, FG1, HVAUX (harness hvaux), I2C (harness i2c), MON (harness mon-data), PWR_AVAIL (harness avail), PWR_SEL (harness pwr_sel), RTC_INT

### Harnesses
mon-data: SCLK, MOSI, MISO, ~{CS}_PV, ADC_CLK, ~{DR}_PV, ~{CS}_MAINS, MOV_BAD, CAL
avail: BIT0, BIT1, BIT2, BIT3, BIT5, BIT4
comp: TX, RX, EN
i2c: SDA, SCL
pwr_sel: SEL_PV, SEL_AC, COMP_PWRD, 12VAUX_~{EN}, 5VAUX_~{EN}, MAINBRD_EN
hvaux: ~{EN}, VSET, UART_P2A, UART_A2P, FC0, FC1, ISET, DEMB

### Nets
3V3_ISO: D10.5(VCC) D24.5(VCC) D26.5(VCC) D30.5(VCC) D53.5(VCC) D55.5(VCC) JP10.1(VDD) JP11.1 JY6.3 R3.2 R7.2 R17.1 R49.2 R147.2 TP4.1
5V_ISO: JY6.2 R72.2
5V_MAIN: L27.1
12V_ISO: JY6.4
12V_MAIN: L28.2
GND_ISO: C67.2 D10.2(GND) D24.2(GND) D26.2(GND) D30.2(GND) D53.2(GND) D55.2(GND) JP10.5(GND) JP11.3 JP11.5 JP11.9 JY6.1 L33.2 LA7.8 R73.1 R82.1 R83.1 R84.1 R151.1 SW1.3 SW1.4 TP5.1
VBAT_UNREG: LA2.5
COMP.EN: JY8.2 NT6.1 ; port COMP.EN
COMP.RX: JY6.8 U15.64(PB03) ; port COMP.RX
COMP.TX: JY6.6 U15.63(PB02) ; port COMP.TX
COMP_ENABLE: JY8.1 NT6.2 U15.50(PB23)
CTL_COMP: D26.6(IO4) JY6.13 LA1.6 R83.2 U15.42(PA21)
CTL_PCOMP: D24.3(IO2) JY8.3 LA3.6 R84.2 RA2.1
DC_OK: D24.1(IO1) LA3.5 U15.31(PA14)
FAN_CTL: D26.3(IO2) LA1.8 R82.2 U15.32(PA15)
FAN_ON: RA5.4 ; port FAN_ON
FG1: D26.1(IO1) LA1.7 RA5.3 ; port FG1
HVAUX.DEMB: D10.1(IO1) JY6.15 TP14.1 U15.40(PB17) ; port HVAUX.DEMB
HVAUX.~{EN}: U15.27(PB14) ; port HVAUX.~{EN}
HVAUX.FC0: D55.6(IO4) JY6.14 RA3.7 ; port HVAUX.FC0
HVAUX.FC1: D55.4(IO3) JY6.16 RA3.8 ; port HVAUX.FC1
HVAUX.ISET: U15.39(PB16) ; port HVAUX.ISET
HVAUX.UART_A2P: JY6.12 RA5.2 ; port HVAUX.UART_A2P
HVAUX.UART_P2A: JY6.10 RA5.1 ; port HVAUX.UART_P2A
HVAUX.VSET: U15.28(PB15) ; port HVAUX.VSET
I2C.SCL: D55.1(IO1) JY6.7 U15.18(PA09) ; port I2C.SCL
I2C.SDA: D55.3(IO2) JY6.5 U15.17(PA08) ; port I2C.SDA
LED0: D3.K JY6.9 U15.29(PA12)
LED1: D1.K JY6.11 U15.30(PA13)
MON.ADC_CLK: RA2.2 ; port MON.ADC_CLK
MON.~{CS}_MAINS: RA3.6 ; port MON.~{CS}_MAINS
MON.~{CS}_PV: RA1.6 ; port MON.~{CS}_PV
MON.CAL: U15.6(PB05) ; port MON.CAL
MON.~{DR}_PV: RA3.5 ; port MON.~{DR}_PV
MON.MISO: R17.2 RA1.5 ; port MON.MISO
MON.MOSI: RA1.7 ; port MON.MOSI
MON.MOV_BAD: U15.62(PB01) ; port MON.MOV_BAD
MON.SCLK: RA1.8 ; port MON.SCLK
nRESET: C67.1 D53.1(IO1) D53.3(IO2) JP10.3(~{RESET}) JP11.10 JY1.3 R7.1 SW1.1 SW1.2 TP6.1 U15.52(~{RESET})
PWR_AVAIL.BIT0: U15.20(PA11) ; port PWR_AVAIL.BIT0
PWR_AVAIL.BIT1: U15.2(PA01) ; port PWR_AVAIL.BIT1
PWR_AVAIL.BIT2: U15.11(PB08) ; port PWR_AVAIL.BIT2
PWR_AVAIL.BIT3: U15.12(PB09) ; port PWR_AVAIL.BIT3
PWR_AVAIL.BIT4: U15.51(PA27) ; port PWR_AVAIL.BIT4
PWR_AVAIL.BIT5: U15.53(PA28) ; port PWR_AVAIL.BIT5
PWR_NRST: D30.6(IO4) JY1.2 LA2.6
PWR_SEL.5VAUX_~{EN}: RA4.8 ; port PWR_SEL.5VAUX_~{EN}
PWR_SEL.12VAUX_~{EN}: RA4.7 ; port PWR_SEL.12VAUX_~{EN}
PWR_SEL.COMP_PWRD: U15.61(PB00) ; port PWR_SEL.COMP_PWRD
PWR_SEL.MAINBRD_EN: U15.19(PA10) ; port PWR_SEL.MAINBRD_EN
PWR_SEL.SEL_AC: TP29.1 U15.60(PB31) ; port PWR_SEL.SEL_AC
PWR_SEL.SEL_PV: TP28.1 U15.59(PB30) ; port PWR_SEL.SEL_PV
PWR_SELECT: D30.1(IO1) JY2.2 LA2.7
PWR_WAKE: D30.3(IO2) LA2.8 U15.3(PA02)
RTC_INT: U15.49(PB22) ; port RTC_INT
SWCLK: D53.6(IO4) JP10.4(SWCLK) JP11.4 R147.1 TP2.1 U15.57(PA30)
SWDIO: D53.4(IO3) JP10.2(SWDIO) JP11.2 TP1.1 U15.58(PA31)
TEST_MODE: JY2.3 R151.2 U15.1(PA00)
TP15: D26.4(IO3) LA1.5 TP15.1
UART2_RXD: D10.4(IO3) LA7.7 RA2.4
UART2_TXD: D10.6(IO4) LA7.6 RA2.3
UART_DAQ2PWR: D24.6(IO4) LA3.8 RA4.6
UART_PWR2DAQ: D24.4(IO3) LA3.7 RA4.5
WAKE_INT: R72.1 R73.2 U15.41(PA20)
NetD1_A: D1.A R49.1
NetD3_A: D3.A R3.1
NetJP9_1: JP9.1 JP9.6 L33.1
NetJP9_2: JP9.2 LA3.4
NetJP9_3: JP9.3 LA3.1
NetJP9_4: JP9.4 LA3.3
NetJP9_5: JP9.5 LA3.2
NetJP9_7: JP9.7 L27.2
NetJP9_8: JP9.8 L28.1
NetJP9_9: JP9.9 LA2.4
NetJP9_10: JP9.10 LA1.1
NetJP9_11: JP9.11 LA2.3
NetJP9_12: JP9.12 LA1.2
NetJP9_13: JP9.13 LA2.2
NetJP9_14: JP9.14 LA1.3
NetJP9_15: JP9.15 LA2.1
NetJP9_16: JP9.16 LA1.4
NetJP12_1: JP12.1(GND) LA7.1
NetJP12_4: JP12.4(PC_TX) LA7.2
NetJP12_5: JP12.5(PC_RX) LA7.3
NetRA1_1: RA1.1 U15.16(PA07)
NetRA1_2: RA1.2 U15.15(PA06)
NetRA1_3: RA1.3 U15.14(PA05)
NetRA1_4: RA1.4 U15.13(PA04)
NetRA2_5: RA2.5 U15.46(PA25)
NetRA2_6: RA2.6 U15.45(PA24)
NetRA2_7: RA2.7 U15.44(PA23)
NetRA2_8: RA2.8 U15.43(PA22)
NetRA3_1: RA3.1 U15.10(PB07)
NetRA3_2: RA3.2 U15.9(PB06)
NetRA3_3: RA3.3 U15.5(PB04)
NetRA3_4: RA3.4 U15.4(PA03)
NetRA4_1: RA4.1 U15.26(PB13)
NetRA4_2: RA4.2 U15.25(PB12)
NetRA4_3: RA4.3 U15.24(PB11)
NetRA4_4: RA4.4 U15.23(PB10)
NetRA5_5: RA5.5 U15.38(PA19)
NetRA5_6: RA5.6 U15.37(PA18)
NetRA5_7: RA5.7 U15.36(PA17)
NetRA5_8: RA5.8 U15.35(PA16)

Not connected (* = marked no-connect by the designer): D10 3(IO2)*; D30 4(IO3)*; JP10 6(SWO)*; JP11 6* 7* 8*; JP12 2(CTS#)* 3(+5V)* 6(RTS#)*; JY1 1*; JY2 1*; LA7 4* 5*

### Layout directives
net class SELV: 3V3_ISO, 5V_ISO, 5V_MAIN, 12V_ISO, 12V_MAIN, COMP.EN, COMP.RX, COMP.TX, COMP_ENABLE, CTL_COMP, CTL_PCOMP, DC_OK, FAN_CTL, FAN_ON, FG1, GND_ISO, HVAUX.DEMB, HVAUX.FC0, HVAUX.FC1, HVAUX.ISET, HVAUX.UART_A2P, HVAUX.UART_P2A, HVAUX.VSET, HVAUX.~{EN}, I2C.SCL, I2C.SDA, LED0, LED1, MON.ADC_CLK, MON.CAL, MON.MISO, MON.MOSI, MON.MOV_BAD, MON.SCLK, MON.~{CS}_MAINS, MON.~{CS}_PV, MON.~{DR}_PV, nRESET, PWR_AVAIL.BIT0, PWR_AVAIL.BIT1, PWR_AVAIL.BIT2, PWR_AVAIL.BIT3, PWR_AVAIL.BIT4, PWR_AVAIL.BIT5, PWR_NRST, PWR_SEL.5VAUX_~{EN}, PWR_SEL.12VAUX_~{EN}, PWR_SEL.COMP_PWRD, PWR_SEL.MAINBRD_EN, PWR_SEL.SEL_AC, PWR_SEL.SEL_PV, PWR_SELECT, PWR_WAKE, RTC_INT, SWCLK, SWDIO, TEST_MODE, TP15, UART2_RXD, UART2_TXD, UART_DAQ2PWR, UART_PWR2DAQ, VBAT_UNREG, WAKE_INT

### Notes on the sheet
- FTDI connector
- (near R147) Place near micro
- (near R147) for noise suppression.
- for serial debug
- (near JP10) Tag-Connect Programming
- Debug/programming
- To wake from sleep
- Substitutes:
- Samtec SHF-105-01-L-D-TH
- FCI 20021511-00010T4LF
- when power returns.
- (near JY6) expansion header
- jumper on 12 for pwrbrd enable (default before R4.0)
- jumper on 23 for ctl enable
- Jumpers by default on 1-2.
- (near JY2) Place on 2-3 for remote
- (near JY2) programming.
- (near LA3) JY2-2 needs to be uncoated for self-test.
- AC_OK output to control.
- Power and data to main board
- Battery-backed power comes back on VBAT_UNREG.
- uC reads COMP and PCOMP from control.
- PCOMP turns on compressor, but uC can
- override it with PCOMP_OVERRIDE
- (near SW1) reset
- COMP doesn't have a purpose.
- FAN_CTL from control processor.
- Probably ignored.
- Fan feedback goes to both processors.
- Licensed under CERN-OHL-P v2, see cover page.

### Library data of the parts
C67 = CAP-00001: as C3 on sheet DCMonitoring
D1 = LED-00005: Red 633nm LED Indication - Discrete 2V 0603 (1608 Metric) 28mcd min, 104mcd typ., diffused; manufacturer: OSRAM Opto Semiconductors Inc.; manufacturer_pn: LS Q976-NR-1; id: 137518
D3 = LED-00006: Yellow 591nm LED Indication - Discrete 2.1V 0603 (1608 Metric) 104mcd clear; manufacturer: Lite-On Inc.; manufacturer_pn: LTST-C191KSKT; id: 137519
D10 D24 D26 D30 D53 D55 = DIO-00013: TVS DIODE 3.3VWM 6VC SOT26; manufacturer: Diodes Incorporated; id: 140046
JP9 = CONN-00065: 16 Positions Header, Shrouded Connector 0.079" (2.00mm) Through Hole Tin; manufacturer_pn: 0559171610; manufacturer: Molex, LLC; id: 139973
JP10 = NOBOM-00009: Tag Connect TC2030 LEGS; manufacturer: New Horizons; id: 138117
JP11 = CONN-00023: 10 Positions Header, Shrouded Connector 0.050" (1.27mm) Through Hole Gold; manufacturer: CNC Tech; manufacturer_pn: 3220-10-0100-00; id: 137220
JP12 = CONN-00034: 6 Positions Header, Unshrouded Connector 0.100" (2.54mm) Through Hole Gold; manufacturer: 3M; manufacturer_pn: 961106-6404-AR; id: 137499
JY1 JY2 JY8 = CONN-00030: 3 Positions Header, Unshrouded Connector 0.100" (2.54mm) Through Hole Gold; manufacturer: 3M; manufacturer_pn: 961103-6404-AR; id: 137495
JY6 = CONN-00121: 16 Positions Header, Unshrouded, Breakaway Connector 0.100" (2.54mm) Through Hole Gold; manufacturer: Sullins Connector Solutions; manufacturer_pn: PRPC008DAAN-RC; id: 173154
L27 L28 L33 = FER-00006: FERRITE BEAD 785 OHM 1812 1LN 50mohm; manufacturer: Wurth Electronics Inc; manufacturer_pn: 742792515; value_text: 785; id: 140504; value: 785
LA1-LA3 LA7 = FER-00009: as LA6 on sheet DCMonitoring
NT6 = NOBOM-00016: Net tie 0.254mm no pads; manufacturer: New Horizons; id: 178547
R3 R49 = RES-00019: RES SMD 200 OHM 1% 1/10W 0603; manufacturer: Panasonic Electronic Components; manufacturer_pn: ERJ-3EKF2000V; id: 137097; value: 200; Key Parameters: 5% OK
R7 R82-R84 = RES-00112: as R142 on sheet DCMonitoring
R17 = RES-00107: as R152 on sheet Cover
R72 = RES-00013: as R35 on sheet DCMonitoring
R73 = RES-00107: 10 kOhms ±1% 0.1W, 1/10W Chip Resistor 0603 (1608 Metric) Automotive AEC-Q200 Thick Film; manufacturer: Panasonic Electronic Components; manufacturer_pn: ERJ-3EKF1002V; id: 182861; value: 10000; Key Parameters: 1% required
R147 R151 = RES-00113: 1 kOhms ±1% 0.1W, 1/10W Chip Resistor 0603 (1608 Metric) Automotive AEC-Q200 Thick Film; manufacturer_pn: ERJ-3EKF1001V; manufacturer: Panasonic Electronic Components; id: 185365; value: 1000; Key Parameters: 1% required
RA1-RA5 = RES-00041: RES ARRAY 4 RES 22 OHM 1206; manufacturer_pn: 742C083220JP; manufacturer: CTS Resistor Products; id: 137388
SW1 = SW-00004: Tactile Switch SPST-NO Top Actuated Through Hole; manufacturer: TE Connectivity ALCOSWITCH Switches; manufacturer_pn: 1825910-2; id: 140502
TP1 TP2 TP4-TP6 TP28 TP29 = NOBOM-00008: as TP10 on sheet DCMonitoring
TP14 TP15 = NOBOM-00007: Test point, TH, 0.78mm (30mil) hole, 1.27mm (50 mil) pad; manufacturer: New Horizons; id: 137437
U15 = MCU-00010: ARM® Cortex®-M0+ SAM D20J Microcontroller IC 32-Bit 48MHz 256KB (256K x 8) FLASH 64-LQFP (10x10); manufacturer: Atmel; id: 169288

## Sheet LVPower.SchDoc
size B; SheetNumber: 6; nhSheetName: LV Power
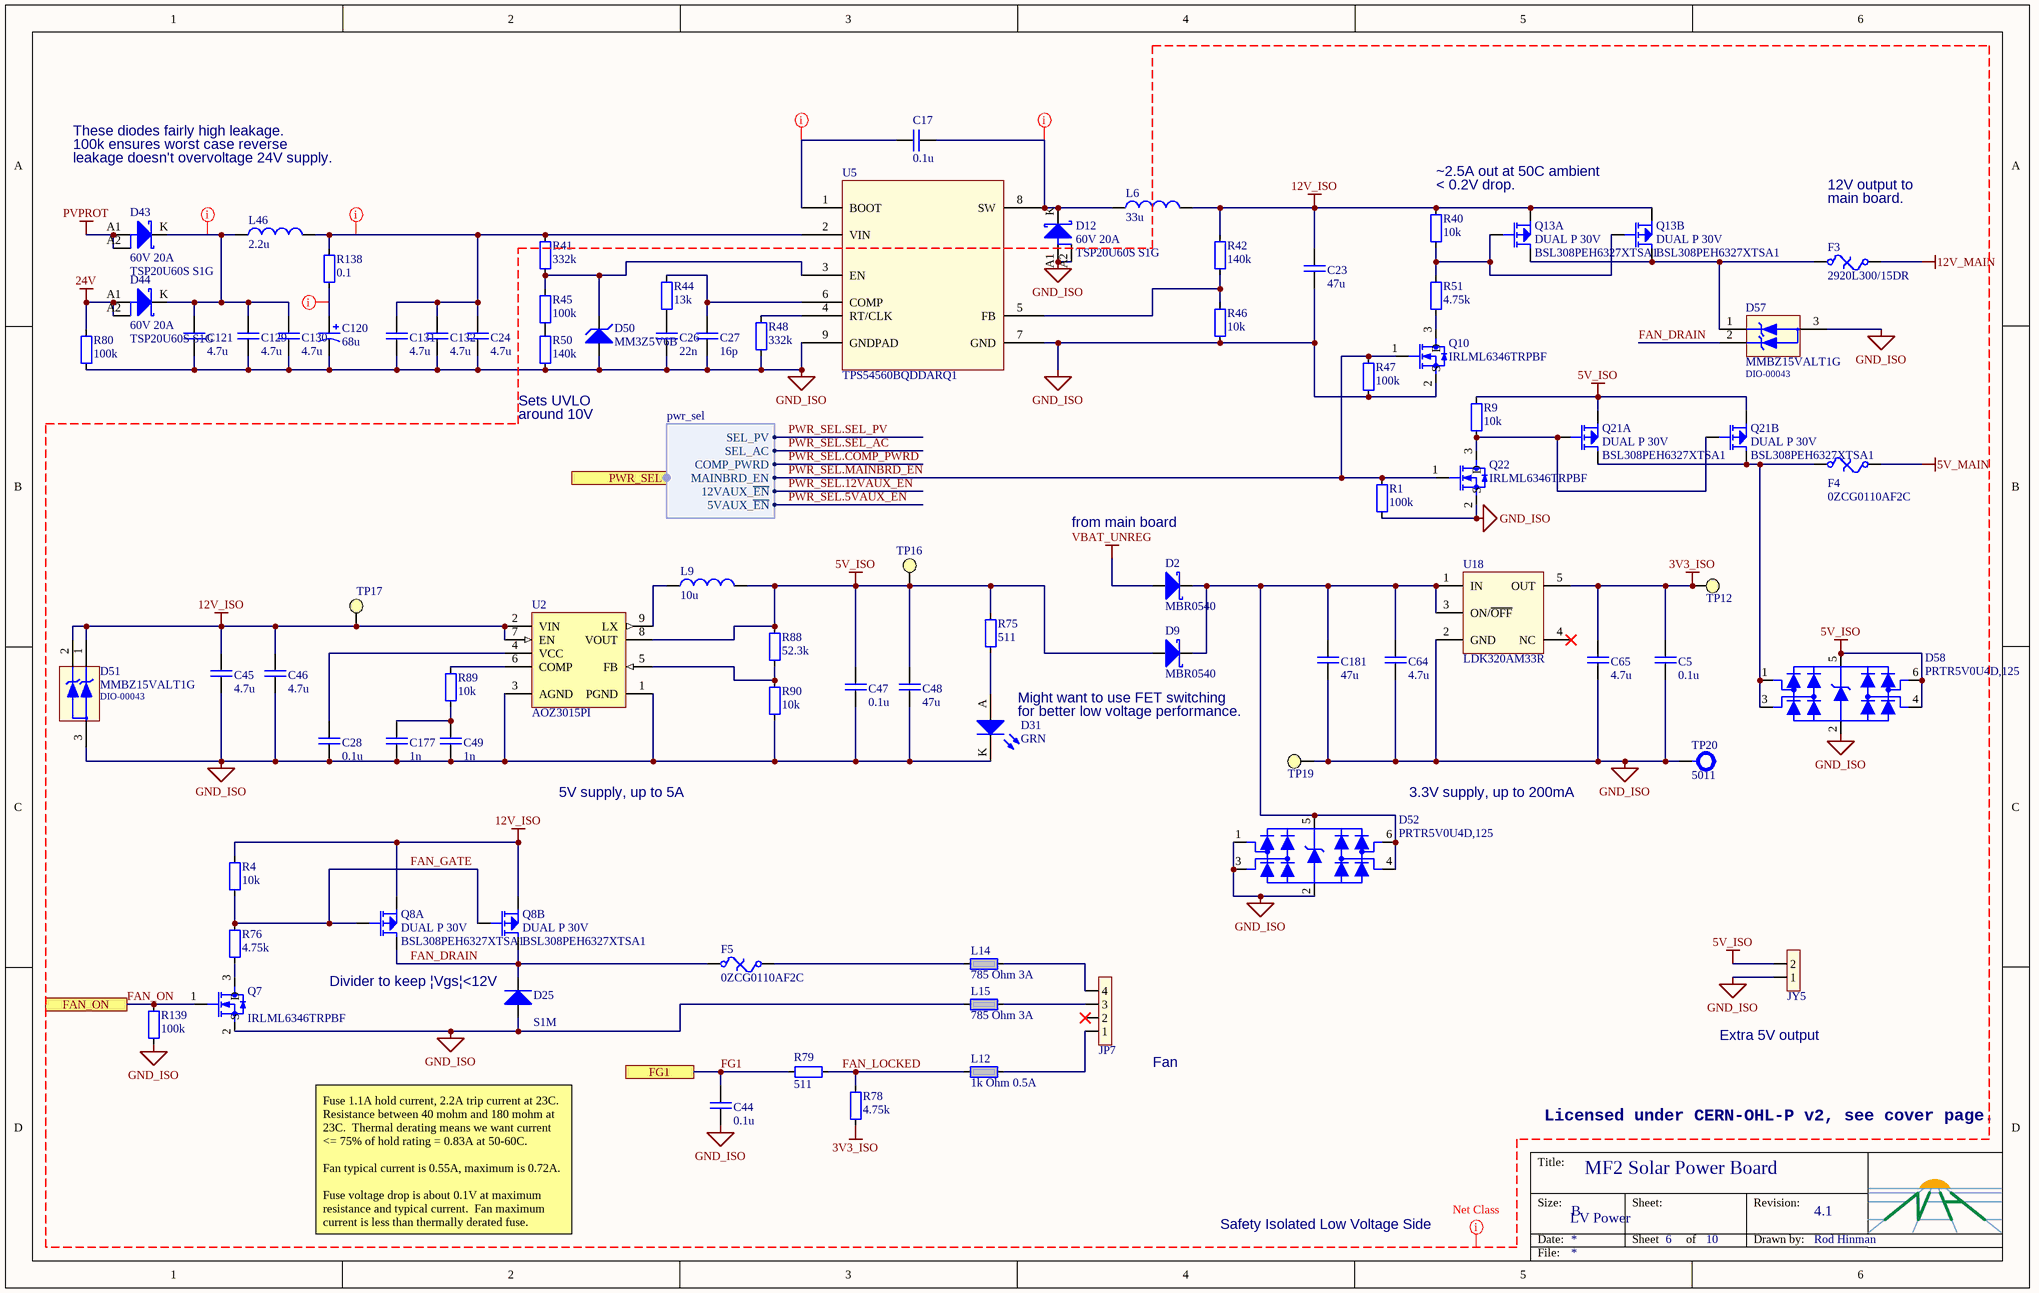
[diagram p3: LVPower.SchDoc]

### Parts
C5  value_text: 0.1u  [CAPC1608X09N[0603]]  (hidden comment: 50V X7R 0603)
C17  value_text: 0.1u  [CAPC1608X09N[0603]]  (hidden comment: 50V X7R 0603)
C23  value_text: 47u  [CAPC3225X270]  (hidden comment: 16V  X5R 1210)
C24  value_text: 4.7u  [CAPC3225X270]  (hidden comment: 100V X5R 1210)
C26  value_text: 22n  [CAPC1608X09N[0603]]  (hidden comment: 50V X7R 0603)
C27  value_text: 16p  [CAPC1608X09N[0603]]  (hidden comment: 50V C0G 0603)
C28  value_text: 0.1u  [CAPC1608X09N[0603]]  (hidden comment: 50V X7R 0603)
C44  value_text: 0.1u  [CAPC1608X09N[0603]]  (hidden comment: 50V X7R 0603)
C45  value_text: 4.7u  [CAPC1608X09N[0603]]  (hidden comment: 25V X6S 0603)
C46  value_text: 4.7u  [CAPC1608X09N[0603]]  (hidden comment: 25V X6S 0603)
C47  value_text: 0.1u  [CAPC1608X09N[0603]]  (hidden comment: 50V X7R 0603)
C48  value_text: 47u  [CAPC3225X270]  (hidden comment: 16V  X5R 1210)
C49  value_text: 1n  [CAPC1608X09N[0603]]  (hidden comment: 50V C0G 0603)
C64  value_text: 4.7u  [CAPC1608X09N[0603]]  (hidden comment: 25V X6S 0603)
C65  value_text: 4.7u  [CAPC1608X09N[0603]]  (hidden comment: 25V X6S 0603)
C120  value_text: 68u  [CAPAE1300X1350D1370DD420L475N]  (hidden comment: 80V Can 20% 320mO)
C121  value_text: 4.7u  [CAPC3225X270]  (hidden comment: 100V X5R 1210)
C129  value_text: 4.7u  [CAPC3225X270]  (hidden comment: 100V X5R 1210)
C130  value_text: 4.7u  [CAPC3225X270]  (hidden comment: 100V X5R 1210)
C131  value_text: 4.7u  [CAPC3225X270]  (hidden comment: 100V X5R 1210)
C132  value_text: 4.7u  [CAPC3225X270]  (hidden comment: 100V X5R 1210)
C177  value_text: 1n  [CAPC1608X09N[0603]]  (hidden comment: 50V C0G 0603)
C181  value_text: 47u  [CAPC3225X270]  (hidden comment: 16V  X5R 1210)
D2  manufacturer_pn: MBR0540  [SOD-123]  (hidden comment: 40V 500mA)
D9  manufacturer_pn: MBR0540  [SOD-123]  (hidden comment: 40V 500mA)
D12  60V 20A  manufacturer_pn: TSP20U60S S1G  [TO-277_Z3N]
D25  manufacturer_pn: S1M  [DO-214AC]  (hidden comment: 1000V 1A)
D31  GRN  [LEDC1608X06NGRN,0603,]
D43  60V 20A  manufacturer_pn: TSP20U60S S1G  [TO-277_Z3N]
D44  60V 20A  manufacturer_pn: TSP20U60S S1G  [TO-277_Z3N]
D50  manufacturer_pn: MM3Z5V6B  [SOD-323F]  (hidden comment: 5.6V 200mW)
D51  manufacturer_pn: MMBZ15VALT1G  partnumber: DIO-00043  [SOT23-3B]  (hidden comment: 12VWM)
D52  manufacturer_pn: PRTR5V0U4D,125  [SOT23-6]  (hidden comment: TVS)
D57  manufacturer_pn: MMBZ15VALT1G  partnumber: DIO-00043  [SOT23-3B]  (hidden comment: 12VWM)
D58  manufacturer_pn: PRTR5V0U4D,125  [SOT23-6]  (hidden comment: TVS)
F3  manufacturer_pn: 2920L300/15DR  [FUSC7351X12N[2920]]  (hidden comment: 15V 3A)
F4  manufacturer_pn: 0ZCG0110AF2C  [Fuse-Bourns-MF-MSMF050-2]  (hidden comment: 1.1A 16V)
F5  manufacturer_pn: 0ZCG0110AF2C  [Fuse-Bourns-MF-MSMF050-2]  (hidden comment: 1.1A 16V)
JP7  JST XH  [JST_B4B-XH-AM(LF)(SN)]  (value not drawn)
JY5  JST XH  [JST_B2B-XH-AM(LF)(SN)]  (value not drawn)
L6  value_text: 33u  [INDUCTOR_VISHAY_IHLP-6767]  (hidden comment: 9A 37mOhm)
L9  value_text: 10u  [INDUCTOR-BOURNS_SRR1280]  (hidden comment: 6A 19.5mOhm)
L12  1k Ohm 0.5A  [INDC2012X110N[0805]]
L14  785 Ohm 3A  [INDC4532X17N[1812]]
L15  785 Ohm 3A  [INDC4532X17N[1812]]
L46  value_text: 2.2u  [INDUCTOR-BOURNS_SRN6045]  (hidden comment: 6A 15mOhm)
Q7  manufacturer_pn: IRLML6346TRPBF  [SOT23-3]  (hidden comment: N-CH 30V 3.4A)
Q8  DUAL P 30V  manufacturer_pn: BSL308PEH6327XTSA1  [SOT_23_6]  (parts A,B of 2)
Q10  manufacturer_pn: IRLML6346TRPBF  [SOT23-3]  (hidden comment: N-CH 30V 3.4A)
Q13  DUAL P 30V  manufacturer_pn: BSL308PEH6327XTSA1  [SOT_23_6]  (parts A,B of 2)
Q21  DUAL P 30V  manufacturer_pn: BSL308PEH6327XTSA1  [SOT_23_6]  (parts A,B of 2)
Q22  manufacturer_pn: IRLML6346TRPBF  [SOT23-3]  (hidden comment: N-CH 30V 3.4A)
R1  value_text: 100k  [RESC1608X05AN[0603]]  (hidden comment: 1/10W 0603 1%)
R4  value_text: 10k  [RESC1608X05AN[0603]]  (hidden comment: 1/10W 0603 1%)
R9  value_text: 10k  [RESC1608X05AN[0603]]  (hidden comment: 1/10W 0603 1%)
R40  value_text: 10k  [RESC1608X05AN[0603]]  (hidden comment: 1/10W 0603 1%)
R41  value_text: 332k  [RESC1608X05AN[0603]]  (hidden comment: 1/10W 0603 1%)
R42  value_text: 140k  [RESC1608X05AN[0603]]  (hidden comment: 1/10W 0603 1%)
R44  value_text: 13k  [RESC1608X05AN[0603]]  (hidden comment: 1/10W 0603 1%)
R45  value_text: 100k  [RESC1608X05AN[0603]]  (hidden comment: 1/10W 0603 1%)
R46  value_text: 10k  [RESC1608X05AN[0603]]  (hidden comment: 1/10W 0603 1%)
R47  value_text: 100k  [RESC1608X05AN[0603]]  (hidden comment: 1/10W 0603 1%)
R48  value_text: 332k  [RESC1608X05AN[0603]]  (hidden comment: 1/10W 0603 1%)
R50  value_text: 140k  [RESC1608X05AN[0603]]  (hidden comment: 1/10W 0603 1%)
R51  value_text: 4.75k  [RESC1608X05AN[0603]]  (hidden comment: 1/10W 0603 1%)
R75  value_text: 511  [RESC1608X05AN[0603]]  (hidden comment: 1/10W 0603 1%)
R76  value_text: 4.75k  [RESC1608X05AN[0603]]  (hidden comment: 1/10W 0603 1%)
R78  value_text: 4.75k  [RESC1608X05AN[0603]]  (hidden comment: 1/10W 0603 1%)
R79  value_text: 511  [RESC1608X05AN[0603]]  (hidden comment: 1/10W 0603 1%)
R80  value_text: 100k  [RESC1608X05AN[0603]]  (hidden comment: 1/10W 0603 1%)
R88  value_text: 52.3k  [RESC1608X05AN[0603]]  (hidden comment: 1/10W 0603 1%)
R89  value_text: 10k  [RESC1608X05AN[0603]]  (hidden comment: 1/10W 0603 1%)
R90  value_text: 10k  [RESC1608X05AN[0603]]  (hidden comment: 1/10W 0603 1%)
R138  value_text: 0.1  [RESC1005X40[0402]]  (hidden comment: 1/16W 0402)
R139  value_text: 100k  [RESC1608X05AN[0603]]  (hidden comment: 1/10W 0603 1%)
TP12  TP SMD 1.5mm  [TP_SMD_Ø1.5mm]  (value not drawn)  (no BOM)
TP16  TP SMD 1.5mm  [TP_SMD_Ø1.5mm]  (value not drawn)  (no BOM)
TP17  TP SMD 1.5mm  [TP_SMD_Ø1.5mm]  (value not drawn)  (no BOM)
TP19  TP SMD 1.5mm  [TP_SMD_Ø1.5mm]  (value not drawn)  (no BOM)
TP20  manufacturer_pn: 5011  [KEYSTONE_5011]  (hidden comment: TP BLK)
U2  AOZ3015  [SOIC127P600X170_HS-9N]  (value not drawn)
U5  manufacturer_pn: TPS54560BQDDARQ1  [SOIC127P600X170_HS-9N]  (hidden comment: 5A)
U18  manufacturer_pn: LDK320AM33R  [TI-SOT-23-5_MC]  (hidden comment: 3.3V 200mA)

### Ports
FAN_ON, FG1, PWR_SEL (harness pwr_sel)

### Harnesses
pwr_sel: SEL_PV, SEL_AC, COMP_PWRD, 12VAUX_~{EN}, 5VAUX_~{EN}, MAINBRD_EN

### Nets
3V3_ISO: C5.1 C65.1 R78.2 TP12.1 U18.5(OUT)
5V_ISO: C47.1 C48.1 D9.A D58.4(IO3) D58.5(VCC) D58.6(IO4) JY5.2 L9.2 Q21.2(S2) Q21.5(S1) R9.2 R75.1 R88.2 TP16.1 U2.8(VOUT)
5V_MAIN: F4.2
12V_ISO: C23.1 C45.1 C46.1 D51.1 D51.2 L6.2 Q8.2(S2) Q8.5(S1) Q13.2(S2) Q13.5(S1) R4.2 R40.2 R42.1 TP17.1 U2.2(VIN) U2.7(EN)
12V_MAIN: F3.2
24V: D44.A1 D44.A2 R80.2
GND_ISO: C5.2 C23.2 C24.2 C26.2 C27.2 C28.2 C44.2 C45.2 C46.2 C47.2 C48.2 C49.2 C64.2 C65.2 C120.- C121.2 C129.2 C130.2 C131.2 C132.2 C177.2 C181.2 D12.A1 D12.A2 D25.A D31.K D50.A D51.3 D52.1(IO1) D52.2(GND) D52.3(IO2) D57.3 D58.2(GND) JY5.1 L15.1 Q7.2(S) Q10.2(S) Q22.2(S) R1.2 R46.2 R47.1 R48.2 R50.2 R80.1 R90.1 R139.2 TP19.1 TP20.1 U2.1(PGND) U2.3(AGND) U5.7(GND) U5.9(GNDPAD) U18.2(GND)
PVPROT: D43.A1 D43.A2
VBAT_UNREG: D2.A
FAN_DRAIN: D25.K D57.2 F5.1 Q8.4(D2) Q8.6(D1)
FAN_GATE: Q8.1(G1) Q8.3(G2) R4.1 R76.1
FAN_LOCKED: L12.1 R78.1 R79.2
FAN_ON: Q7.1(G) R139.1 ; port FAN_ON
FG1: C44.1 R79.1 ; port FG1
PWR_SEL.MAINBRD_EN: Q10.1(G) Q22.1(G) R1.1 R47.2 ; port PWR_SEL.MAINBRD_EN
NetC17_1: C17.1 U5.1(BOOT)
NetC17_2: C17.2 D12.K L6.1 U5.8(SW)
NetC24_1: C24.1 C131.1 C132.1 L46.2 R41.1 R138.1 U5.2(VIN)
NetC26_1: C26.1 R44.2
NetC27_1: C27.1 R44.1 U5.6(COMP)
NetC28_1: C28.1 U2.4(VCC)
NetC49_1: C49.1 C177.1 R89.1
NetC64_1: C64.1 C181.1 D2.K D9.K D52.4(IO3) D52.5(VCC) D52.6(IO4) U18.1(IN) U18.3(ON/~{OFF})
NetC120_+: C120.+ R138.2
NetC121_1: C121.1 C129.1 C130.1 D43.K D44.K L46.1
NetD31_A: D31.A R75.2
NetD50_K: D50.K R41.2 R45.2 U5.3(EN)
NetD57_1: D57.1 F3.1 Q13.4(D2) Q13.6(D1)
NetD58_1: D58.1(IO1) D58.3(IO2) F4.1 Q21.4(D2) Q21.6(D1)
NetF5_2: F5.2 L14.1
NetJP7_1: JP7.1 L12.2
NetJP7_3: JP7.3 L15.2
NetJP7_4: JP7.4 L14.2
NetL9_1: L9.1 U2.9(LX)
NetQ7_3: Q7.3(D) R76.2
NetQ10_3: Q10.3(D) R51.2
NetQ13_1: Q13.1(G1) Q13.3(G2) R40.1 R51.1
NetQ21_1: Q21.1(G1) Q21.3(G2) Q22.3(D) R9.1
NetR42_2: R42.2 R46.1 U5.5(FB)
NetR45_1: R45.1 R50.1
NetR48_1: R48.1 U5.4(RT/CLK)
NetR88_1: R88.1 R90.2 U2.5(FB)
NetR89_2: R89.2 U2.6(COMP)

Not connected (* = marked no-connect by the designer): JP7 2*; U18 4(NC)*

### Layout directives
net class SELV: 3V3_ISO, 5V_ISO, 5V_MAIN, 12V_ISO, 12V_MAIN, 24V, FAN_DRAIN, FAN_GATE, FAN_LOCKED, FAN_ON, FG1, GND_ISO, PVPROT, PWR_SEL.5VAUX_~{EN}, PWR_SEL.12VAUX_~{EN}, PWR_SEL.COMP_PWRD, PWR_SEL.MAINBRD_EN, PWR_SEL.SEL_AC, PWR_SEL.SEL_PV, VBAT_UNREG
net class PVPOS: NetC17_1, NetC17_2, NetC24_1, NetC120_+, NetC121_1

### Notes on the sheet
- These diodes fairly high leakage.
- 100k ensures worst case reverse
- leakage doesn't overvoltage 24V supply.
- |.5A out at 50C ambient
- < 0.2V drop.
- 12V output to
- main board.
- (near R50) Sets UVLO
- around 10V
- from main board
- Might want to use FET switching
- (near D31) for better low voltage performance.
- 5V supply, up to 5A
- (near D52) 3.3V supply, up to 200mA
- (near D25) Divider to keep ¦Vgs¦<12V
- (near JY5) Extra 5V output
- Fan
- Licensed under CERN-OHL-P v2, see cover page.
- Fuse 1.1A hold current, 2.2A trip current at 23C.  Resistance between 40 mohm and 180 mohm at 23C.  Thermal derating means we want current <= 75% of hold rating = 0.83A at 50-60C.
  Fan typical current is 0.55A, maximum is 0.72A.
  Fuse voltage drop is about 0.1V at maximum resistance and typical current.  Fan maximum current is less than thermally derated fuse.
- Safety Isolated Low Voltage Side

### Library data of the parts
C5 C17 C28 C44 C47 = CAP-00001: as C3 on sheet DCMonitoring
C23 C48 C181 = CAP-00050: 47µF ±20% 16V Ceramic Capacitor X5R 1210 (3225 Metric); manufacturer: Murata Electronics North America; manufacturer_pn: GRM32ER61C476ME15L; id: 147646; value: 4.7E-5; Key Parameters: V >= 16V
C24 C121 C129-C132 = CAP-00075: 4.7µF ±10% 100V Ceramic Capacitor X5R 1210 (3225 Metric); manufacturer: Taiyo Yuden; manufacturer_pn: HMK325BJ475KM-PE; id: 171762; value: 4.7E-6; Key Parameters: V >= 50V preferred, 25V possible
C26 = CAP-00035: 0.022µF 50V Ceramic Capacitor X7R 0603 (1608 Metric) 0.063" L x 0.031" W (1.60mm x 0.80mm); manufacturer: Murata Electronics North America; manufacturer_pn: GRM188R71H223KA01D; id: 137516; value: 2.2E-8; Key Parameters: v >= 16V
C27 = CAP-00051: 16pF ±5% 50V Ceramic Capacitor C0G, NP0 0603 (1608 Metric); manufacturer: Murata Electronics North America; manufacturer_pn: GRM1885C1H160JA01D; id: 147785; value: 1.6E-11; Key Parameters: V >= 16V
C45 C46 C64 C65 = CAP-00015: as C6 on sheet DCMonitoring
C49 C177 = CAP-00053: 1000pF ±5% 50V Ceramic Capacitor C0G, NP0 0603 (1608 Metric); manufacturer: Murata Electronics North America; manufacturer_pn: GRM1885C1H102JA01D; id: 147791; value: 1E-9; Key Parameters: V >= 25V
C120 = CAP-00072: 68µF 80V Aluminum Electrolytic Capacitors Radial, Can - SMD 5000 Hrs @ 105°C; manufacturer: Panasonic Electronic Components; manufacturer_pn: EEV-FK1K680Q; id: 169906; value: 6.8E-5; Key Parameters: V >= 50V preferred, 25V possible
D2 D9 = DIO-00007: Diode Schottky 40V 500mA Surface Mount SOD-123; manufacturer: Fairchild Semiconductor; id: 137137
D12 D43 D44 = DIO-00037: Diode Schottky 60V 20A Surface Mount TO-277A (SMPC); manufacturer: Taiwan Semiconductor Corporation; id: 193255
D25 = DIO-00009: Diode Standard 1000V (1kV) 1A Surface Mount SMA (DO-214AC); manufacturer: Fairchild Semiconductor; id: 137139
D31 = LED-00007: Green 571nm LED Indication - Discrete 2V 0603 (1608 Metric) 35mcd clear; manufacturer_pn: LTST-C191KGKT; manufacturer: Lite-On Inc.; id: 137520
D50 = DIO-00042: Zener Diode 5.6V 200mW ±2% Surface Mount SOD-323F; manufacturer: ON Semiconductor; id: 363924
D51 D57 = DIO-00043: 21V Clamp 1.9A Ipp Tvs Diode Surface Mount SOT-23-3 (TO-236); manufacturer: ON Semiconductor; id: 363926
D52 D58 = DIO-00000: TVS DIODE 6TSOP; manufacturer: Nexperia USA Inc.; id: 136479
F3 = FUSE-00010: Polymeric PTC Resettable Fuse 15V 3A Ih Surface Mount 2920 (7351 Metric), Concave; manufacturer: Littelfuse Inc.; id: 199285
F4 F5 = FUSE-00016: Polymeric PTC Resettable Fuse 16V 1.1A Ih Surface Mount 1812 (4532 Metric), Concave; manufacturer: Bel Fuse Inc.; id: 237617
JP7 = CONN-00064: 4 Positions Header, Shrouded Connector 0.098" (2.50mm) Through Hole Tin; manufacturer: JST Sales America Inc.; manufacturer_pn: B4B-XH-AM(LF)(SN); id: 139972
JY5 = CONN-00072: 2 Positions Header, Shrouded Connector 0.098" (2.50mm) Through Hole Tin; manufacturer_pn: B2B-XH-AM(LF)(SN); manufacturer: JST Sales America Inc.; id: 140465
L6 = IND-00013: 33µH Shielded Molded Inductor 10.7A 37 mOhm Max Nonstandard; manufacturer_pn: IHLP6767GZER330M11; manufacturer: Vishay Dale; id: 147638; value: 3.3E-5
L9 = IND-00008: 10µH Shielded Wirewound Inductor 6A 19.5 mOhm Max Nonstandard; manufacturer: Bourns Inc.; manufacturer_pn: SRR1280-100M; id: 140505; value: 1E-5
L12 = FER-00005: as L5 on sheet DCMonitoring
L14 L15 = FER-00006: as L27 on sheet Microcontroller
L46 = IND-00023: 2.2µH Semi-Shielded Wirewound Inductor 6A 15 mOhm Nonstandard; manufacturer_pn: SRN6045TA-2R2Y; manufacturer: Bourns Inc.; id: 170438; value: 2.2E-6
Q7 Q10 Q22 = FET-00002: as Q11 on sheet DCMonitoring
Q8 Q13 Q21 = FET-00023: as Q39 on sheet DCMonitoring
R1 R139 = RES-00112: 100 kOhms ±1% 0.1W, 1/10W Chip Resistor 0603 (1608 Metric) Automotive AEC-Q200 Thick Film; manufacturer_pn: ERJ-3EKF1003V; manufacturer: Panasonic Electronic Components; id: 185358; value: 100000; Key Parameters: 1% required
R4 R9 R40 R89 R90 = RES-00107: as R73 on sheet Microcontroller
R41 R48 = RES-00064: RES SMD 332K OHM 1% 1/10W 0603; manufacturer_pn: ERJ-3EKF3323V; manufacturer: Panasonic Electronic Components; id: 147650; value: 332000; Key Parameters: 1% required
R42 R50 = RES-00063: RES SMD 140K OHM 1% 1/10W 0603; manufacturer_pn: ERJ-3EKF1403V; manufacturer: Panasonic Electronic Components; id: 147649; value: 140000; Key Parameters: 1% required
R44 = RES-00062: RES SMD 13.0K OHM 1% 1/10W 0603; manufacturer_pn: ERJ-3EKF1302V; manufacturer: Panasonic Electronic Components; id: 147648; value: 13000; Key Parameters: 1% required
R45 R47 R80 = RES-00112: as R142 on sheet DCMonitoring
R46 = RES-00107: as R152 on sheet Cover
R51 R76 R78 = RES-00013: as R35 on sheet DCMonitoring
R75 = RES-00035: RES SMD 511 OHM 1% 1/10W 0603; manufacturer_pn: ERJ-3EKF5110V; manufacturer: Panasonic Electronic Components; id: 137113; value: 511; Key Parameters: 5% OK
R79 = RES-00035: RES SMD 511 OHM 1% 1/10W 0603; manufacturer: Panasonic Electronic Components; manufacturer_pn: ERJ-3EKF5110V; id: 137113; value: 511; Key Parameters: 5% OK
R88 = RES-00031: RES SMD 52.3K OHM 1% 1/10W 0603; manufacturer: Panasonic Electronic Components; manufacturer_pn: ERJ-3EKF5232V; id: 137109; value: 52300; Key Parameters: 1% required
R138 = RES-00097: RES SMD 0.1 OHM 1% 1/6W 0402; manufacturer_pn: ERJ-2BSFR10X; manufacturer: Panasonic Electronic Components; id: 169912; value: 0.1; Key Parameters: 5% OK
TP12 TP16 TP17 TP19 = NOBOM-00008: as TP10 on sheet DCMonitoring
TP20 = CONN-00028: TEST POINT PC MULTI PURPOSE BLK; manufacturer: Keystone Electronics; id: 137441
U2 = ICPWR-00018: Buck Switching Regulator IC Positive Adjustable 0.8V 1 Output 3A 8-SOIC (0.154in, 3.90mm Width) Exposed Pad; manufacturer: Alpha & Omega Semiconductor Inc.; id: 148346
U5 = ICPWR-00044: Buck, Split Rail Switching Regulator IC Positive Adjustable 0.8V 1 Output 5A 8-PowerSOIC (0.154", 3.90mm Width); manufacturer: Texas Instruments; id: 363923
U18 = ICPWR-00039: Linear Voltage Regulator IC Positive Fixed 1 Output 3.3V 200mA SOT-23-5; manufacturer: STMicroelectronics; id: 236192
